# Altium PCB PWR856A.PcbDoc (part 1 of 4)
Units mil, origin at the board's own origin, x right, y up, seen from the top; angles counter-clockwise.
Board outline 4000 x 4000 mil, 8 copper layers (Top Layer, Signal Layer 1, Signal Layer 2, Signal Layer 3, Signal Layer 4, Signal Layer 5, Signal Layer 6, Bottom Layer), stack 60.4 mil thick; 246 components, 78 nets, 563 pads, 817 vias.
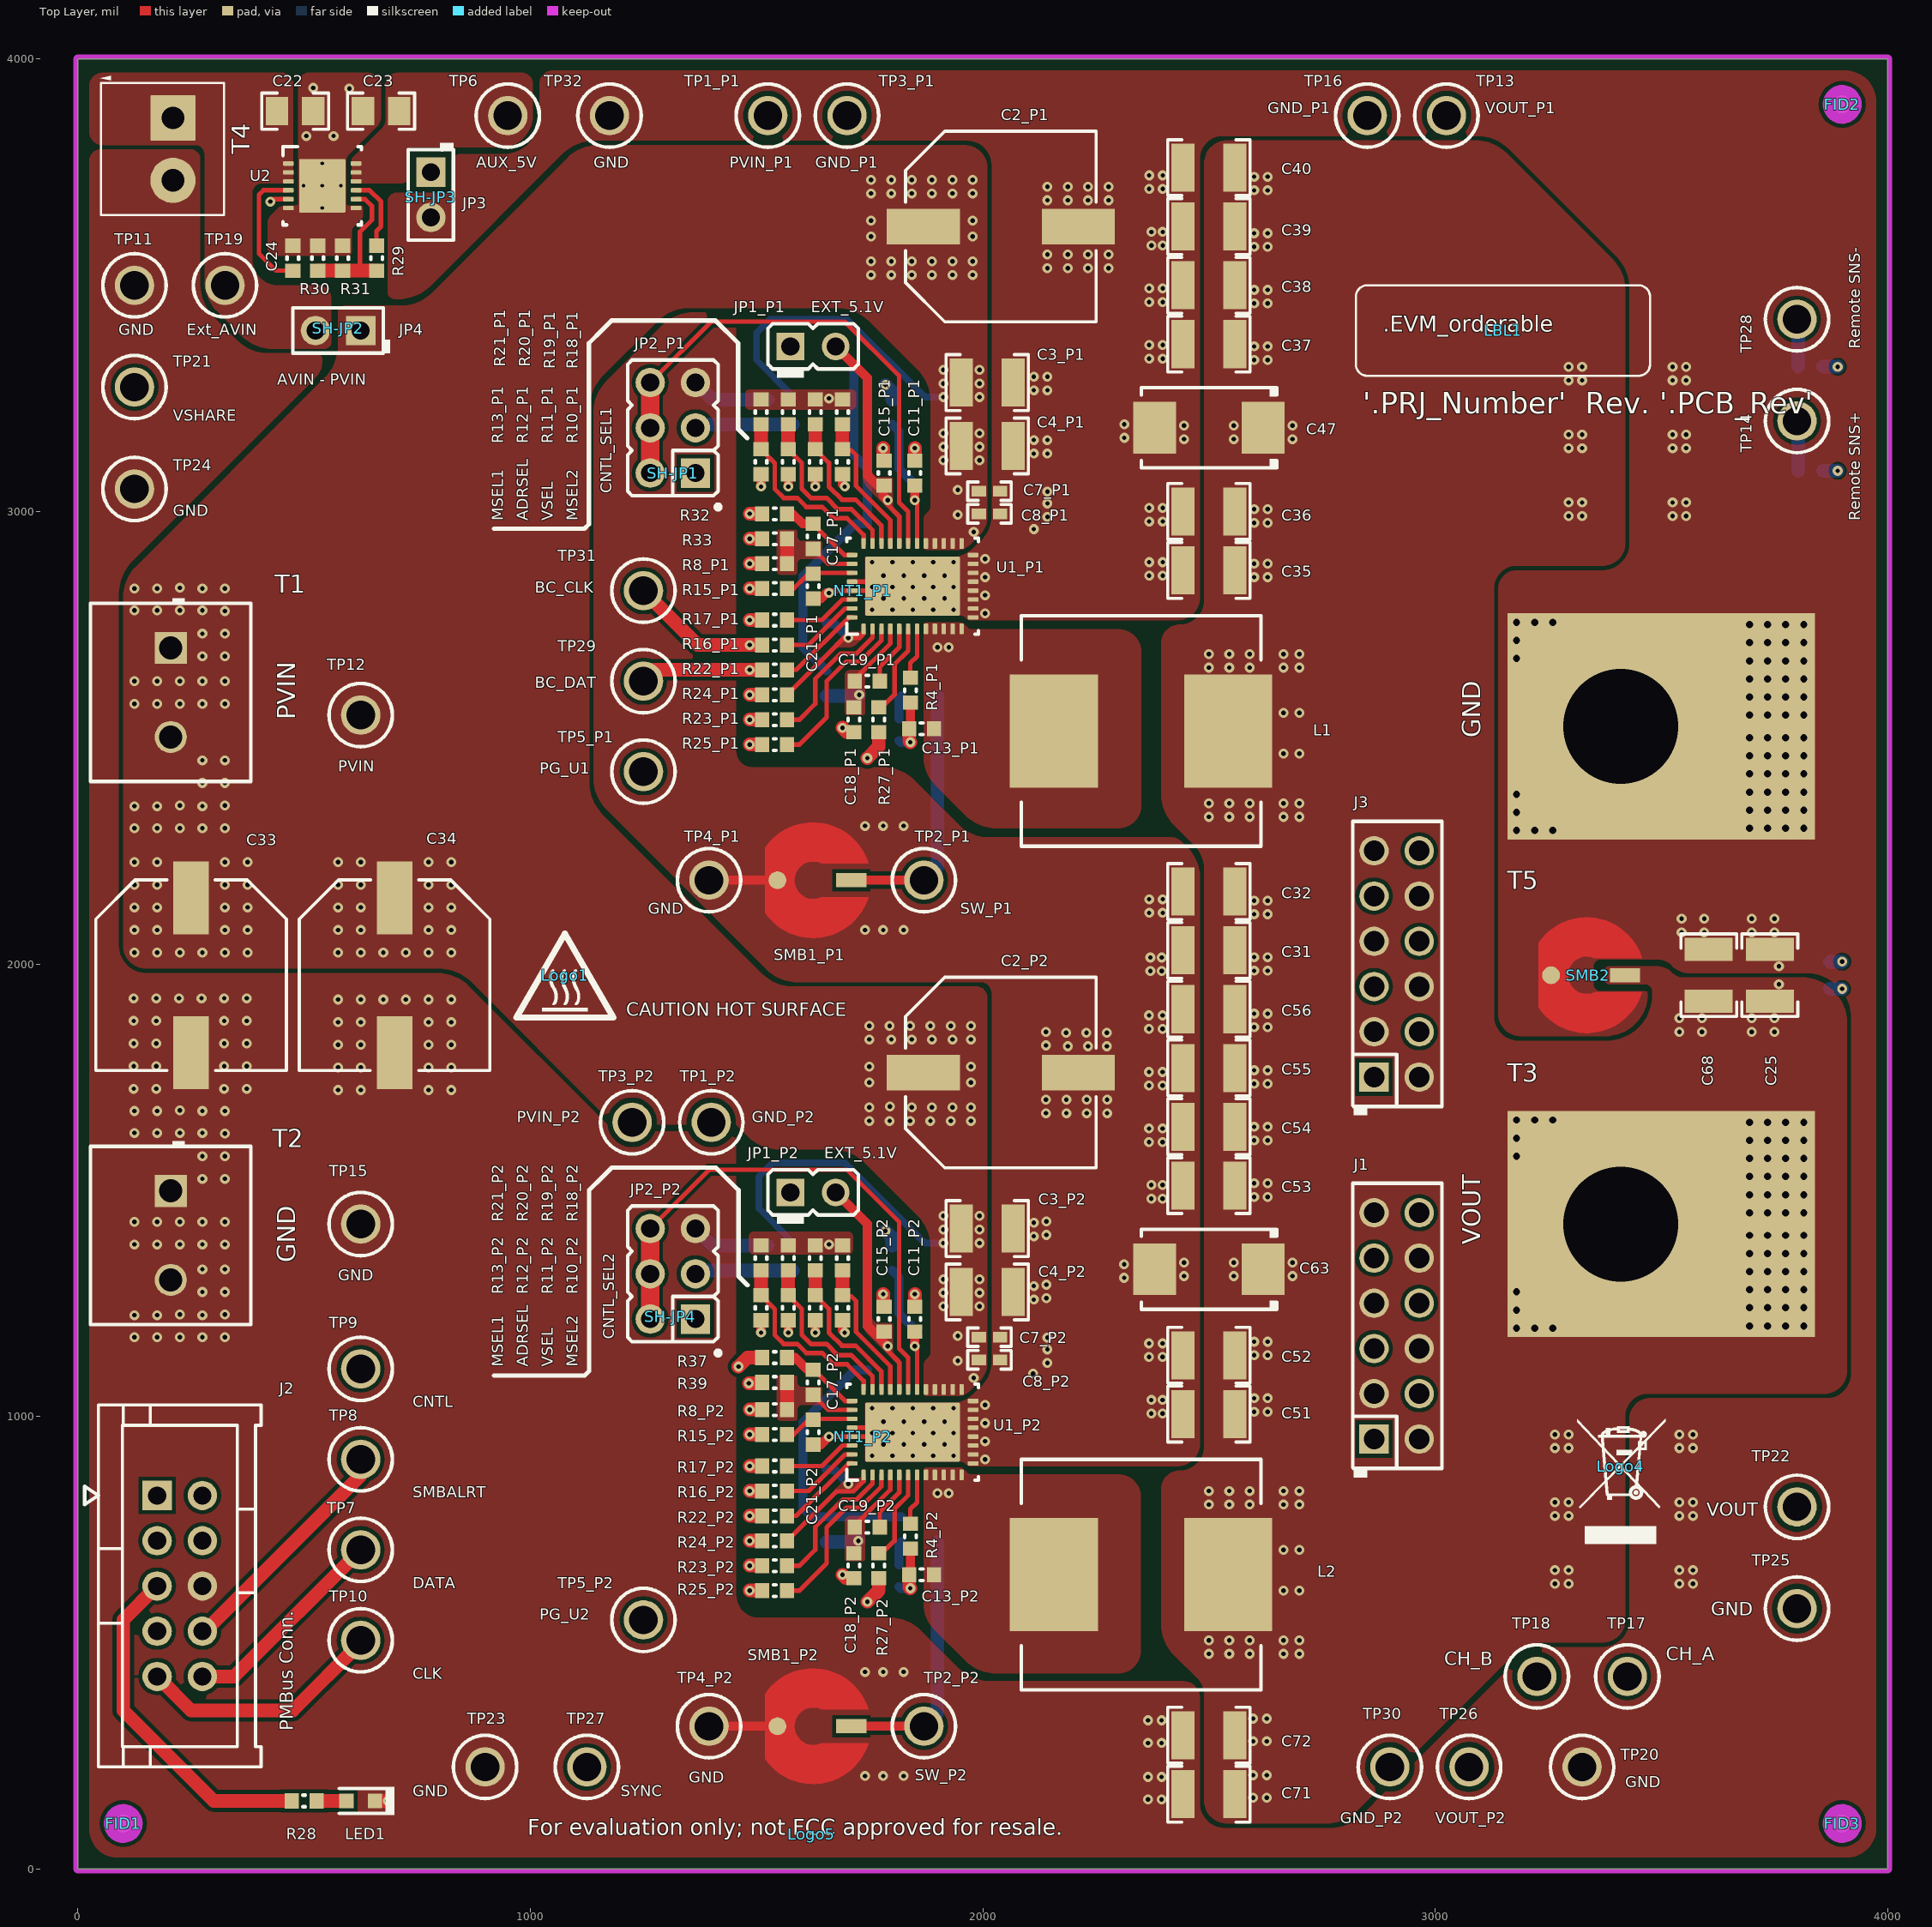
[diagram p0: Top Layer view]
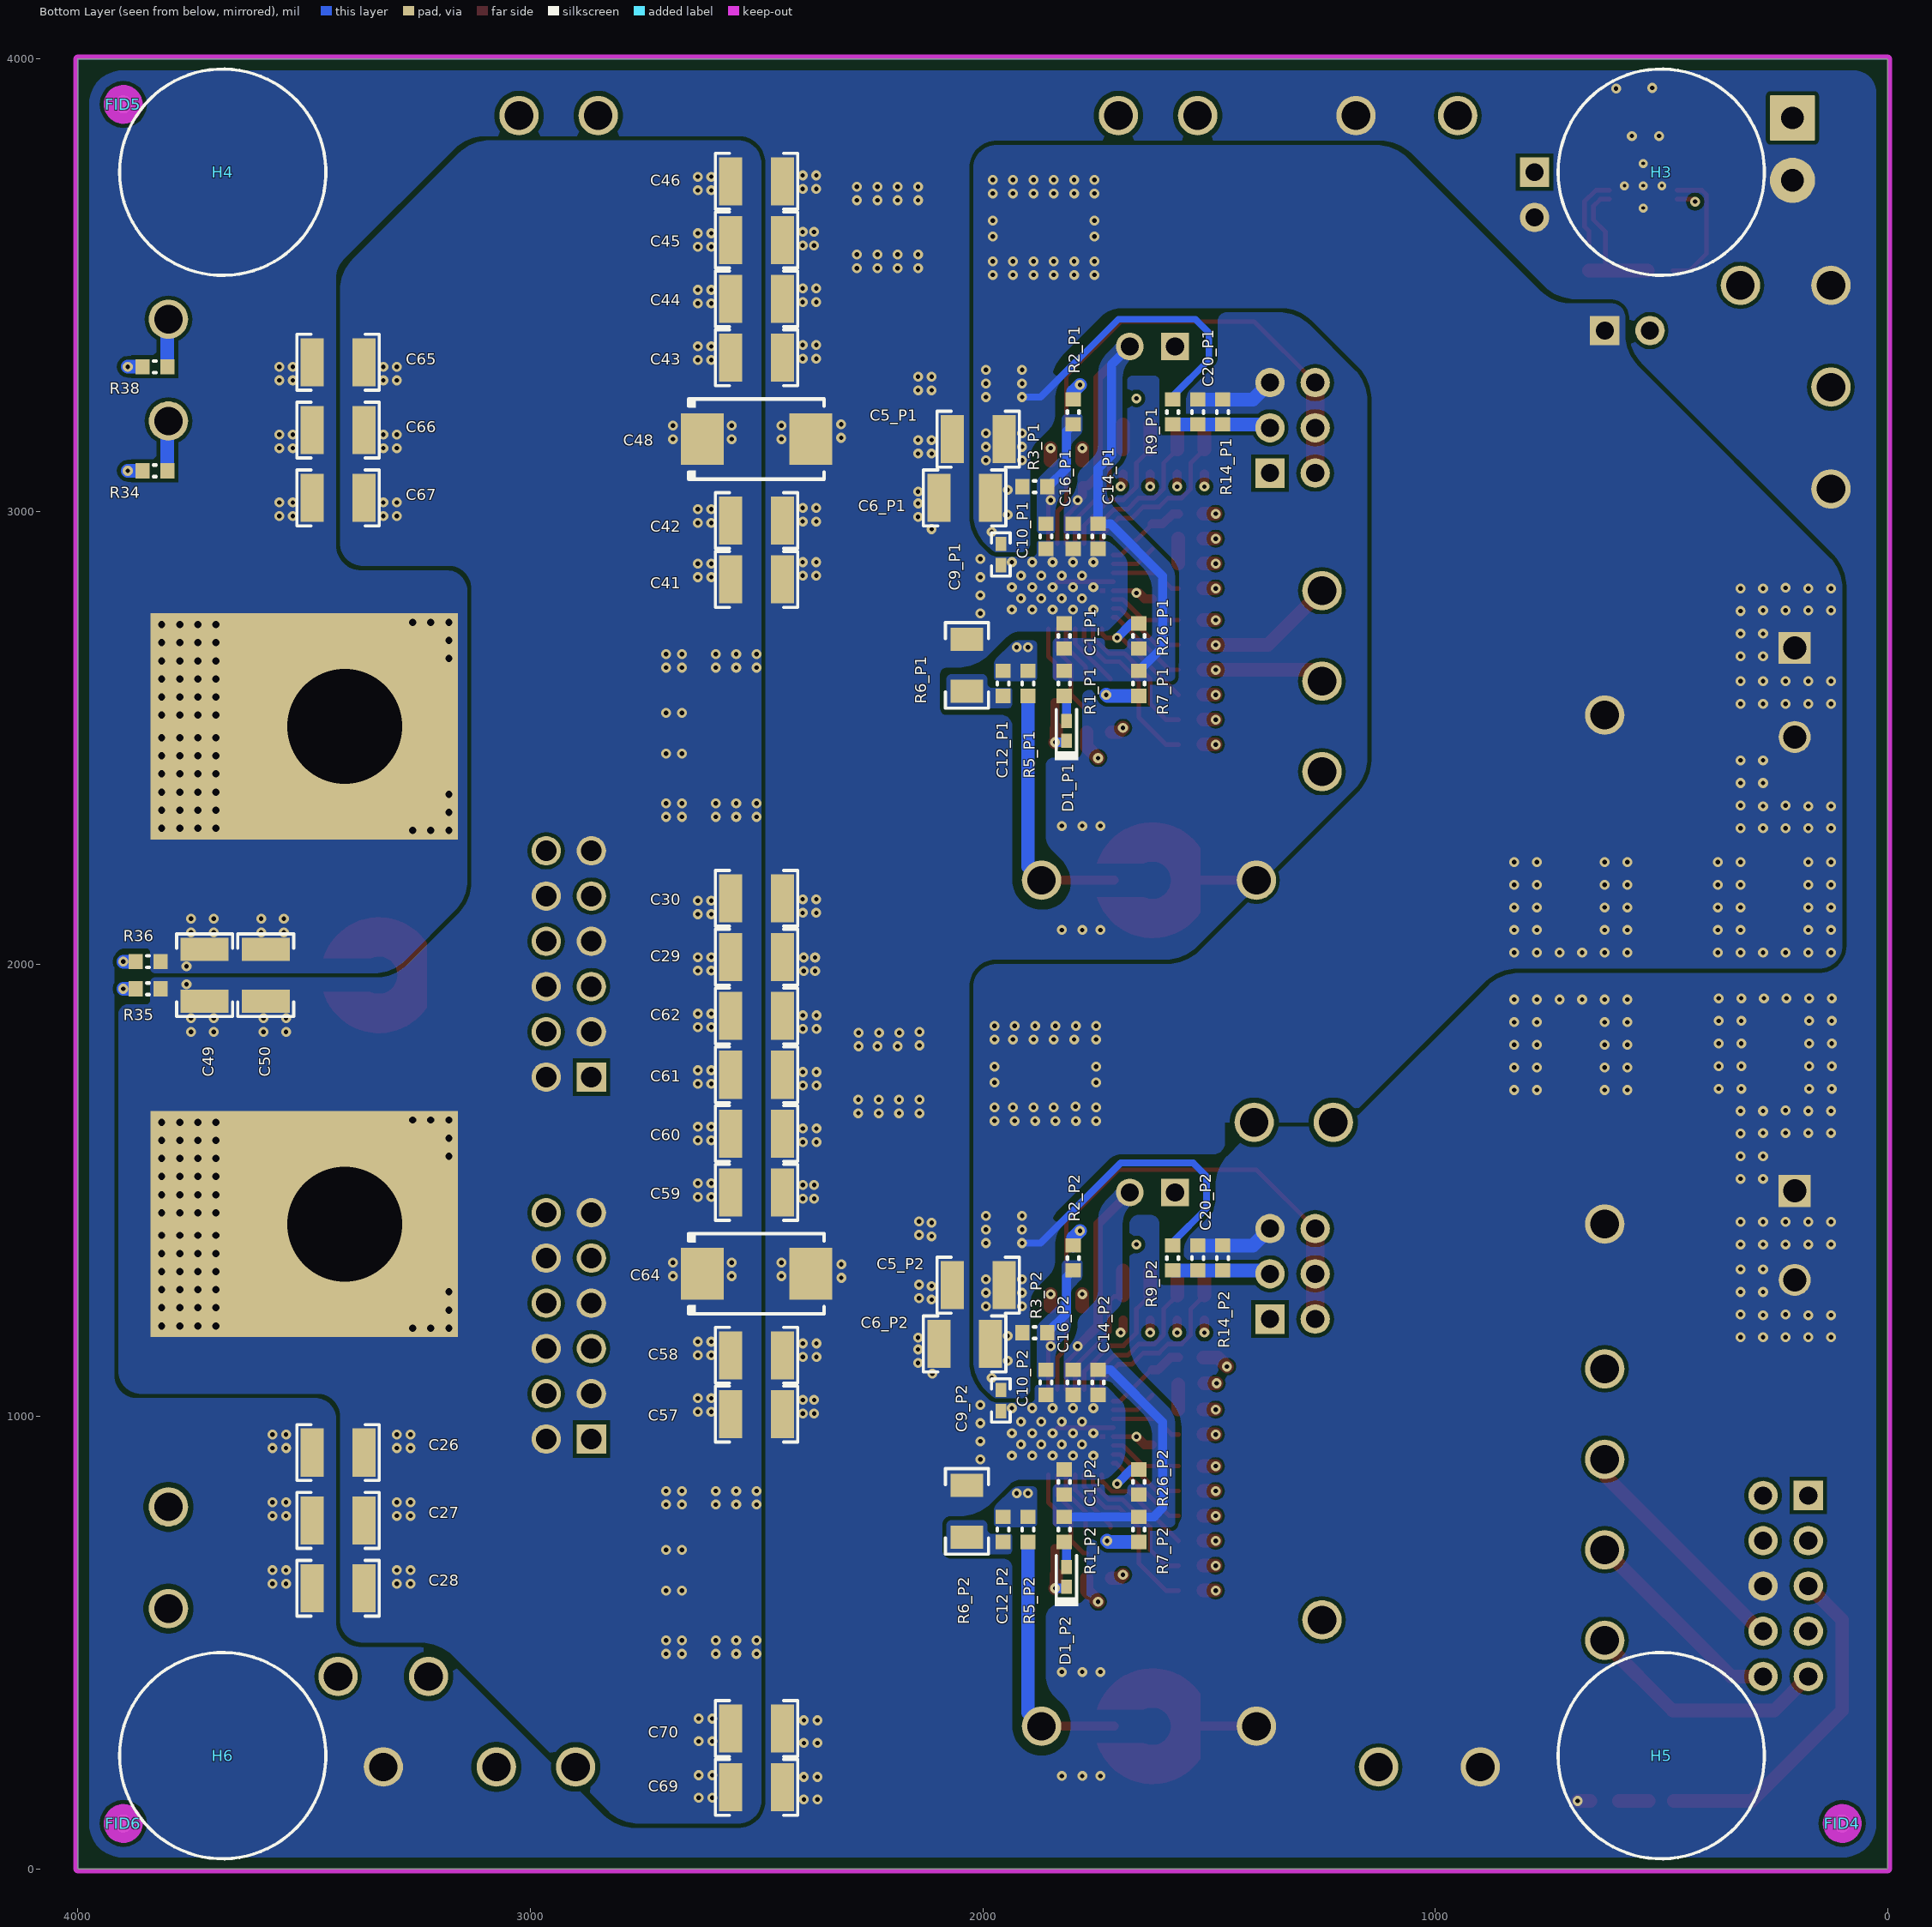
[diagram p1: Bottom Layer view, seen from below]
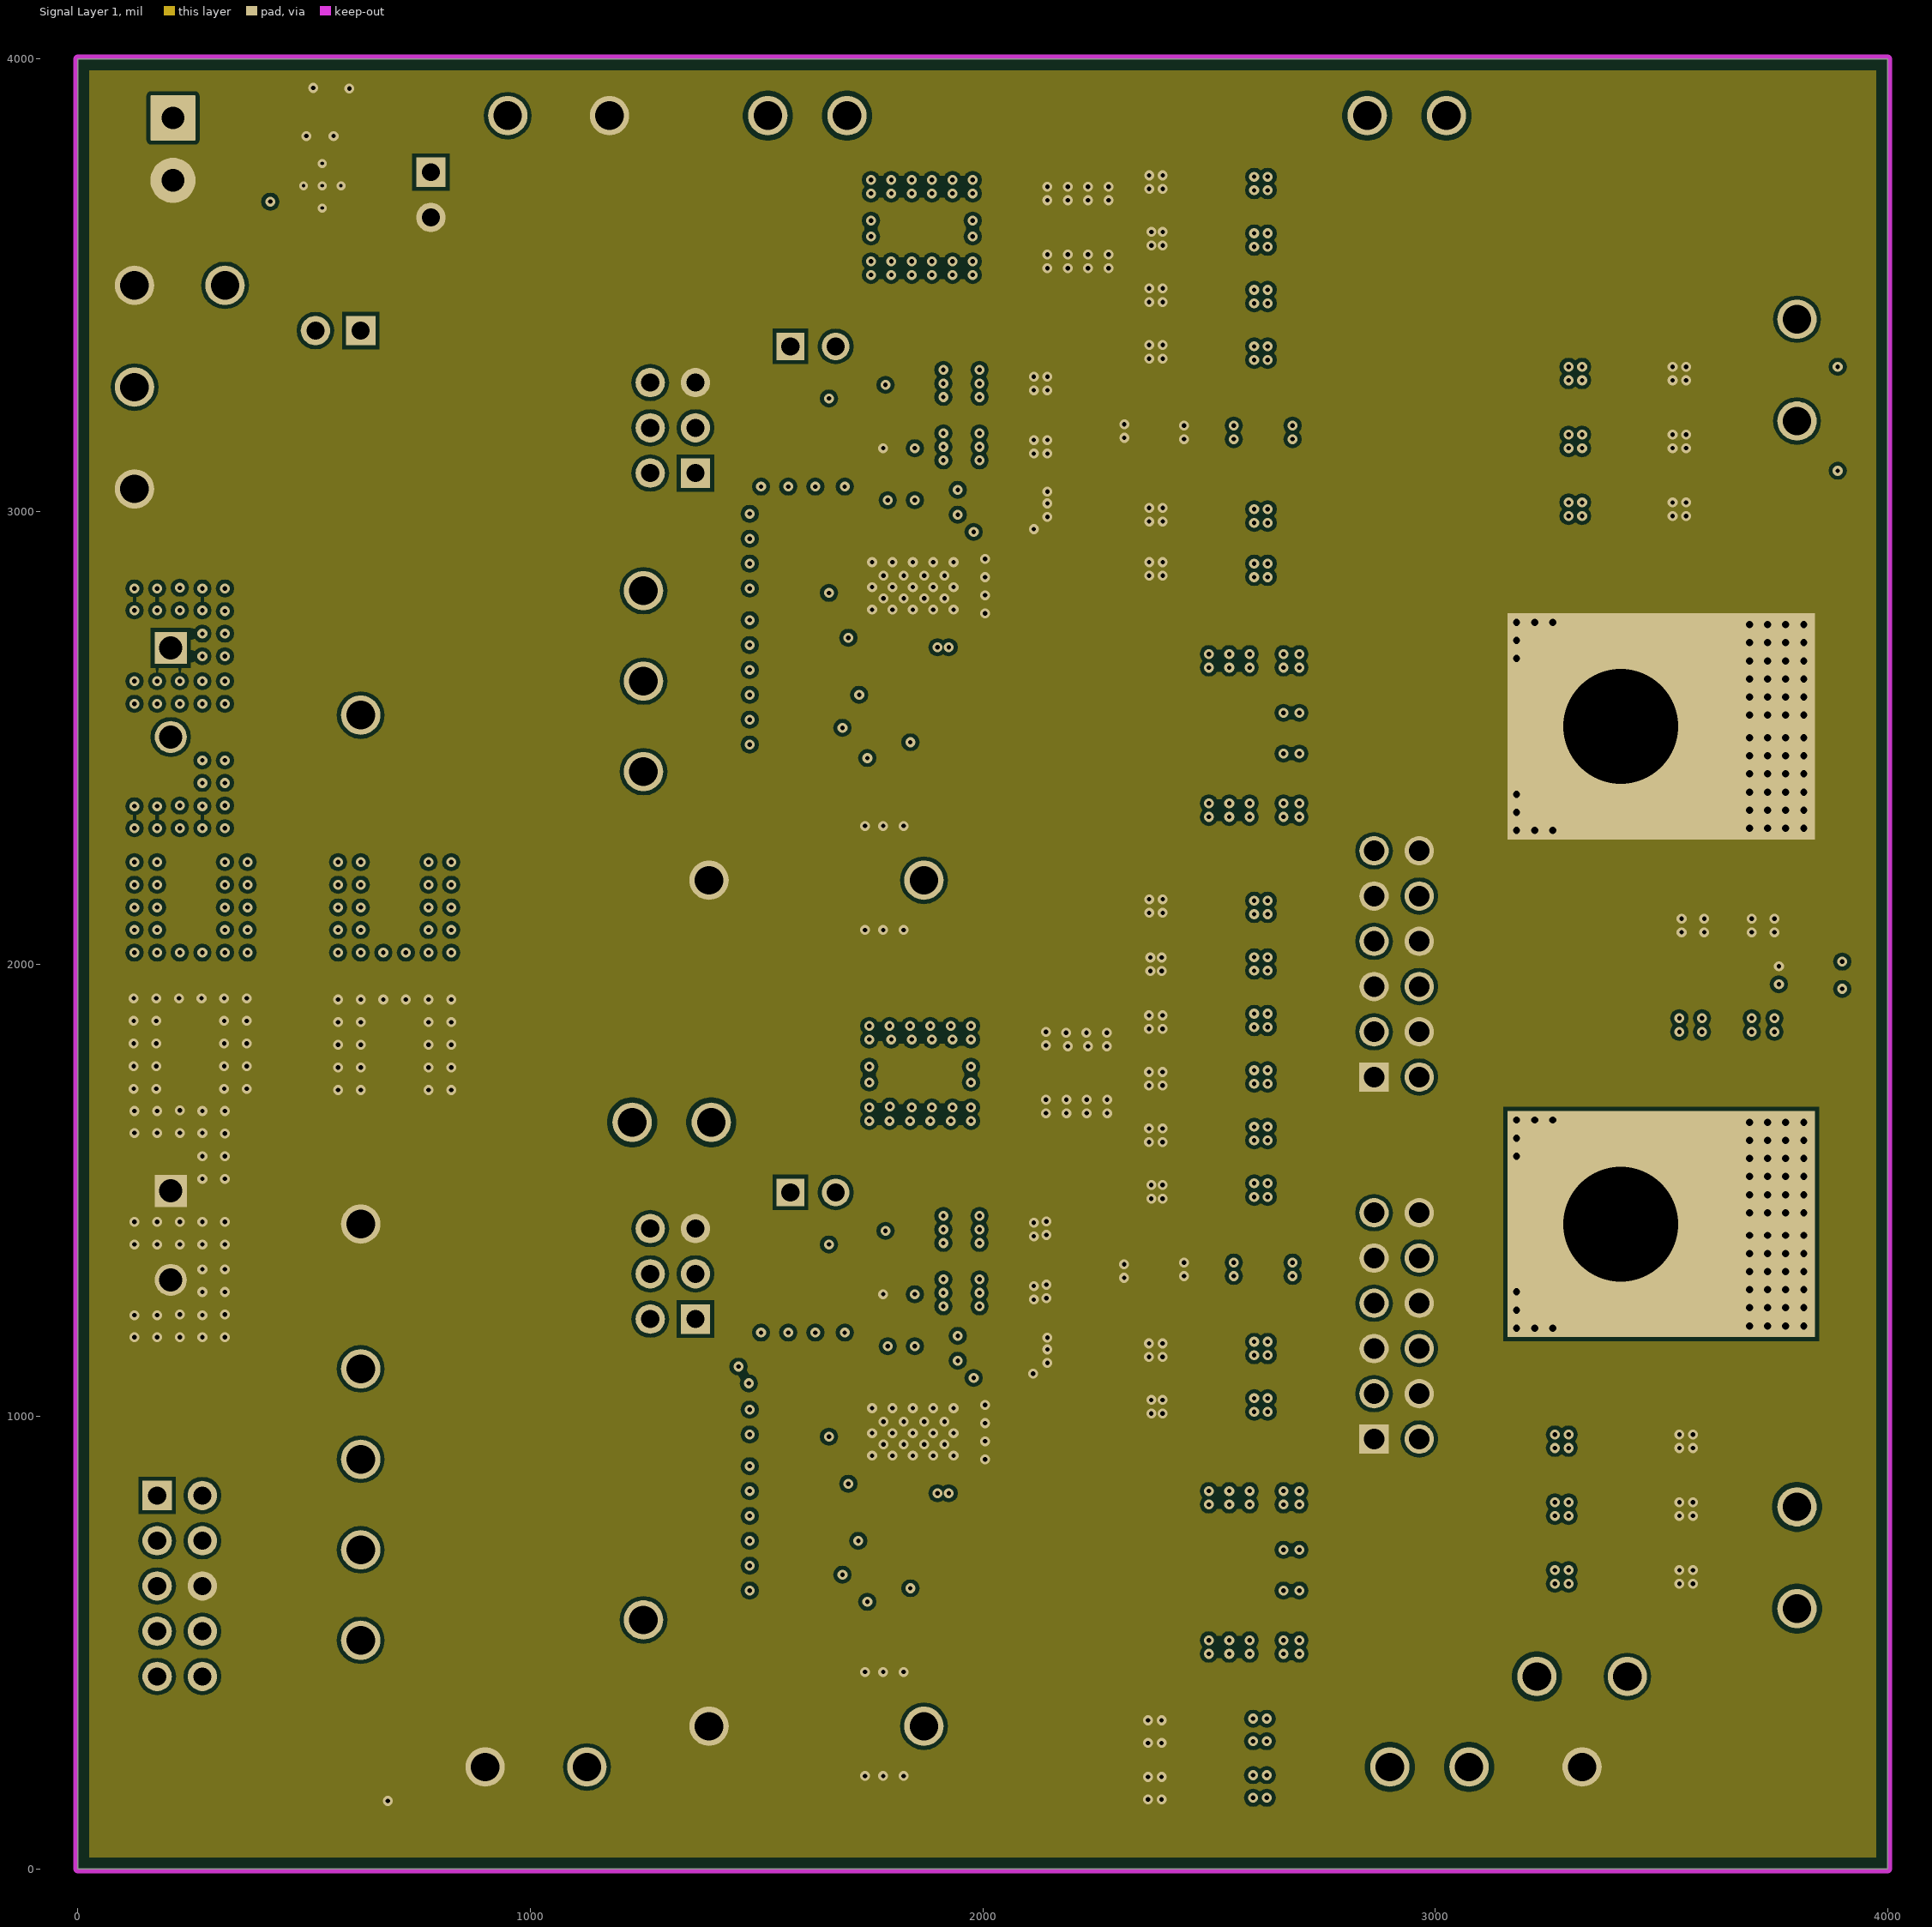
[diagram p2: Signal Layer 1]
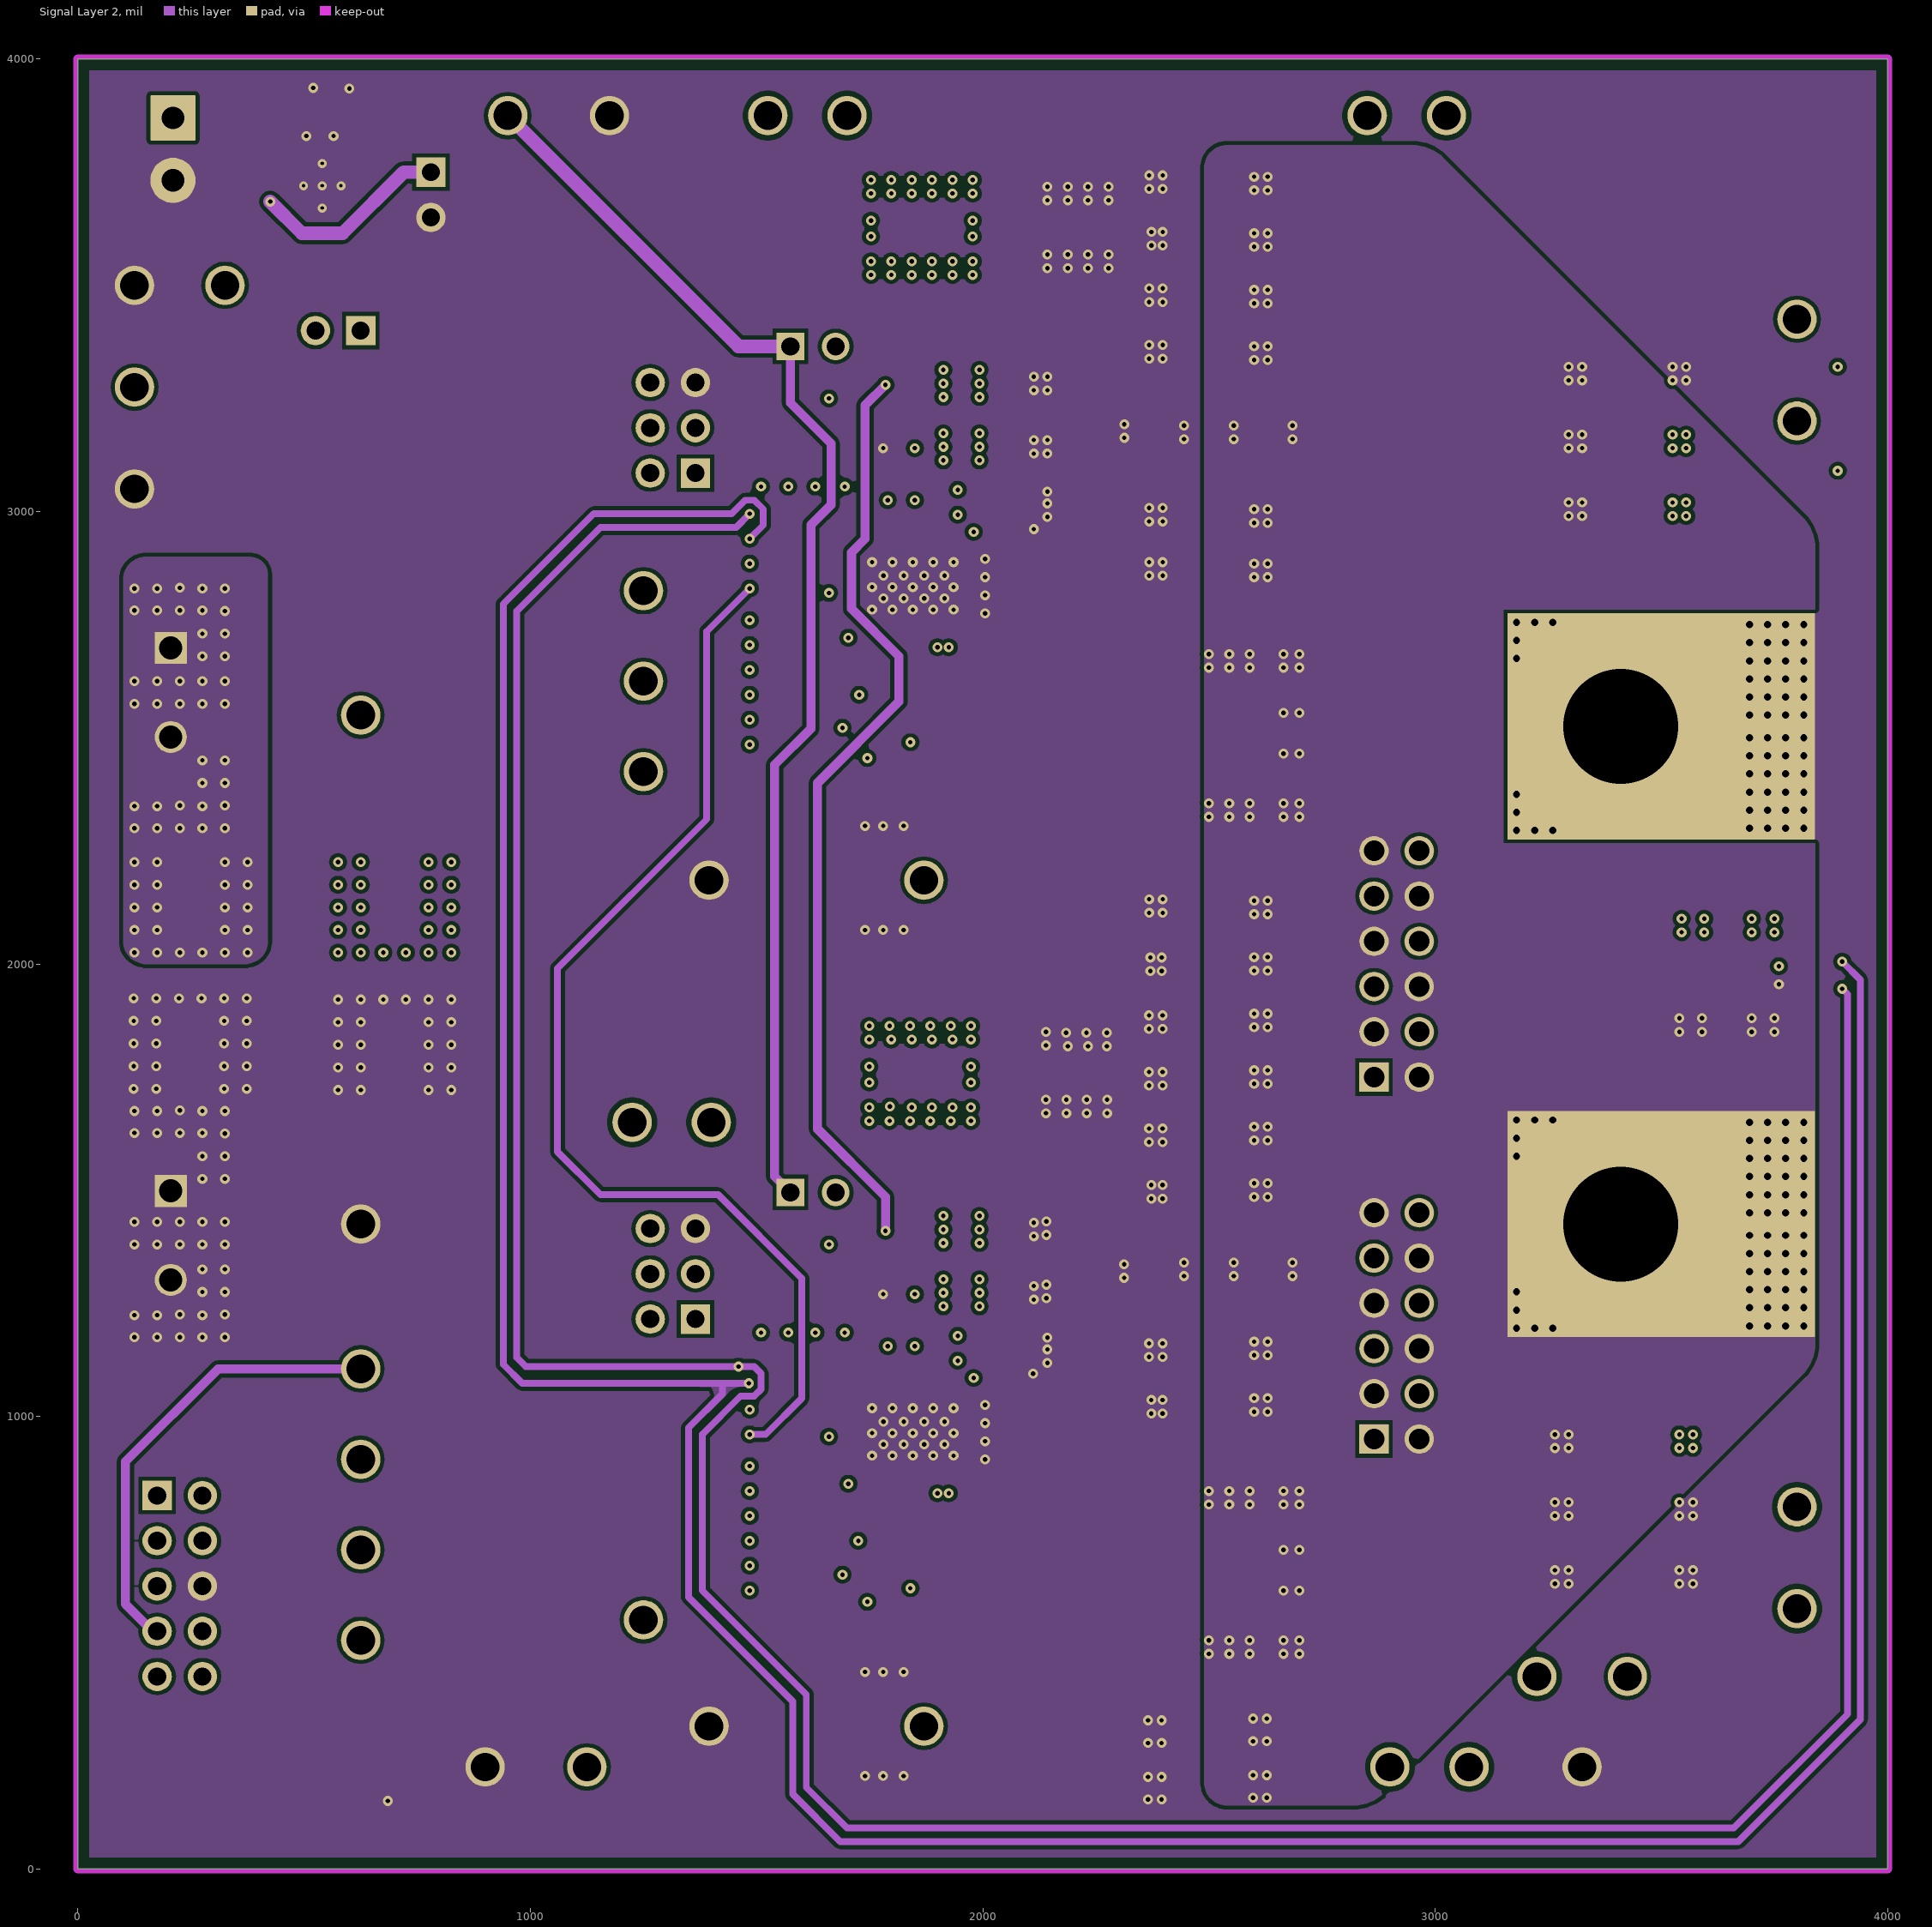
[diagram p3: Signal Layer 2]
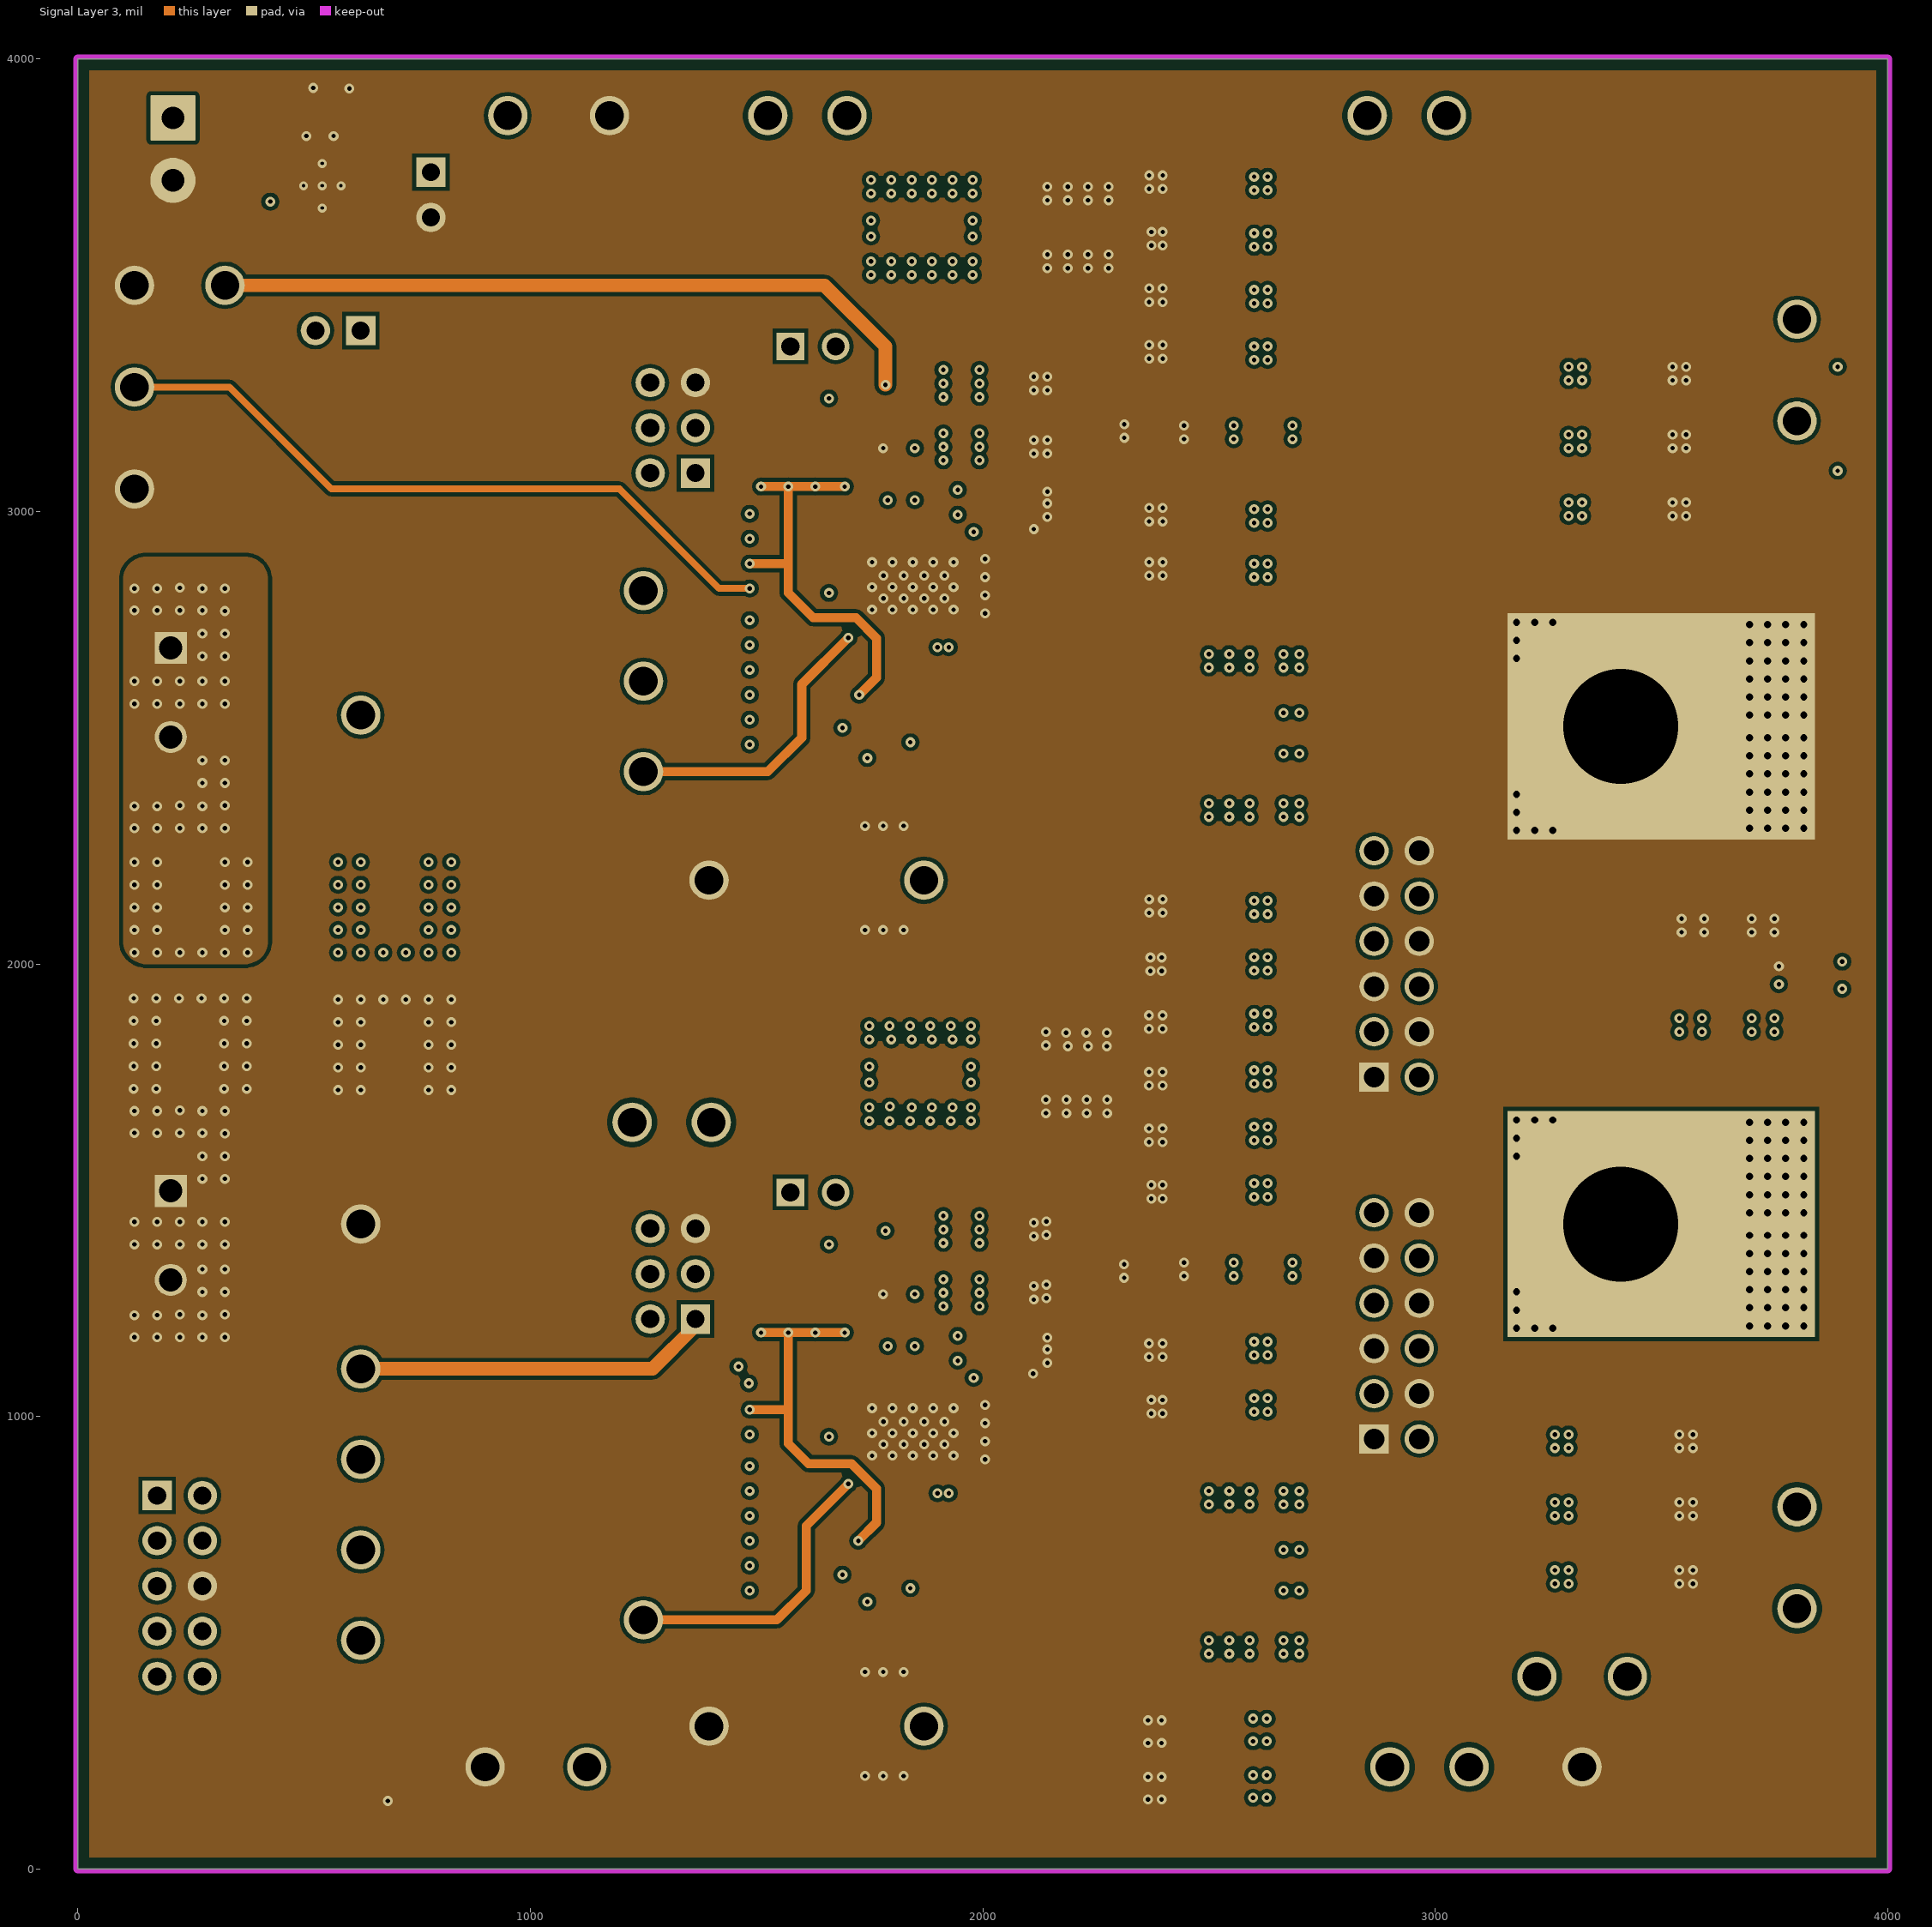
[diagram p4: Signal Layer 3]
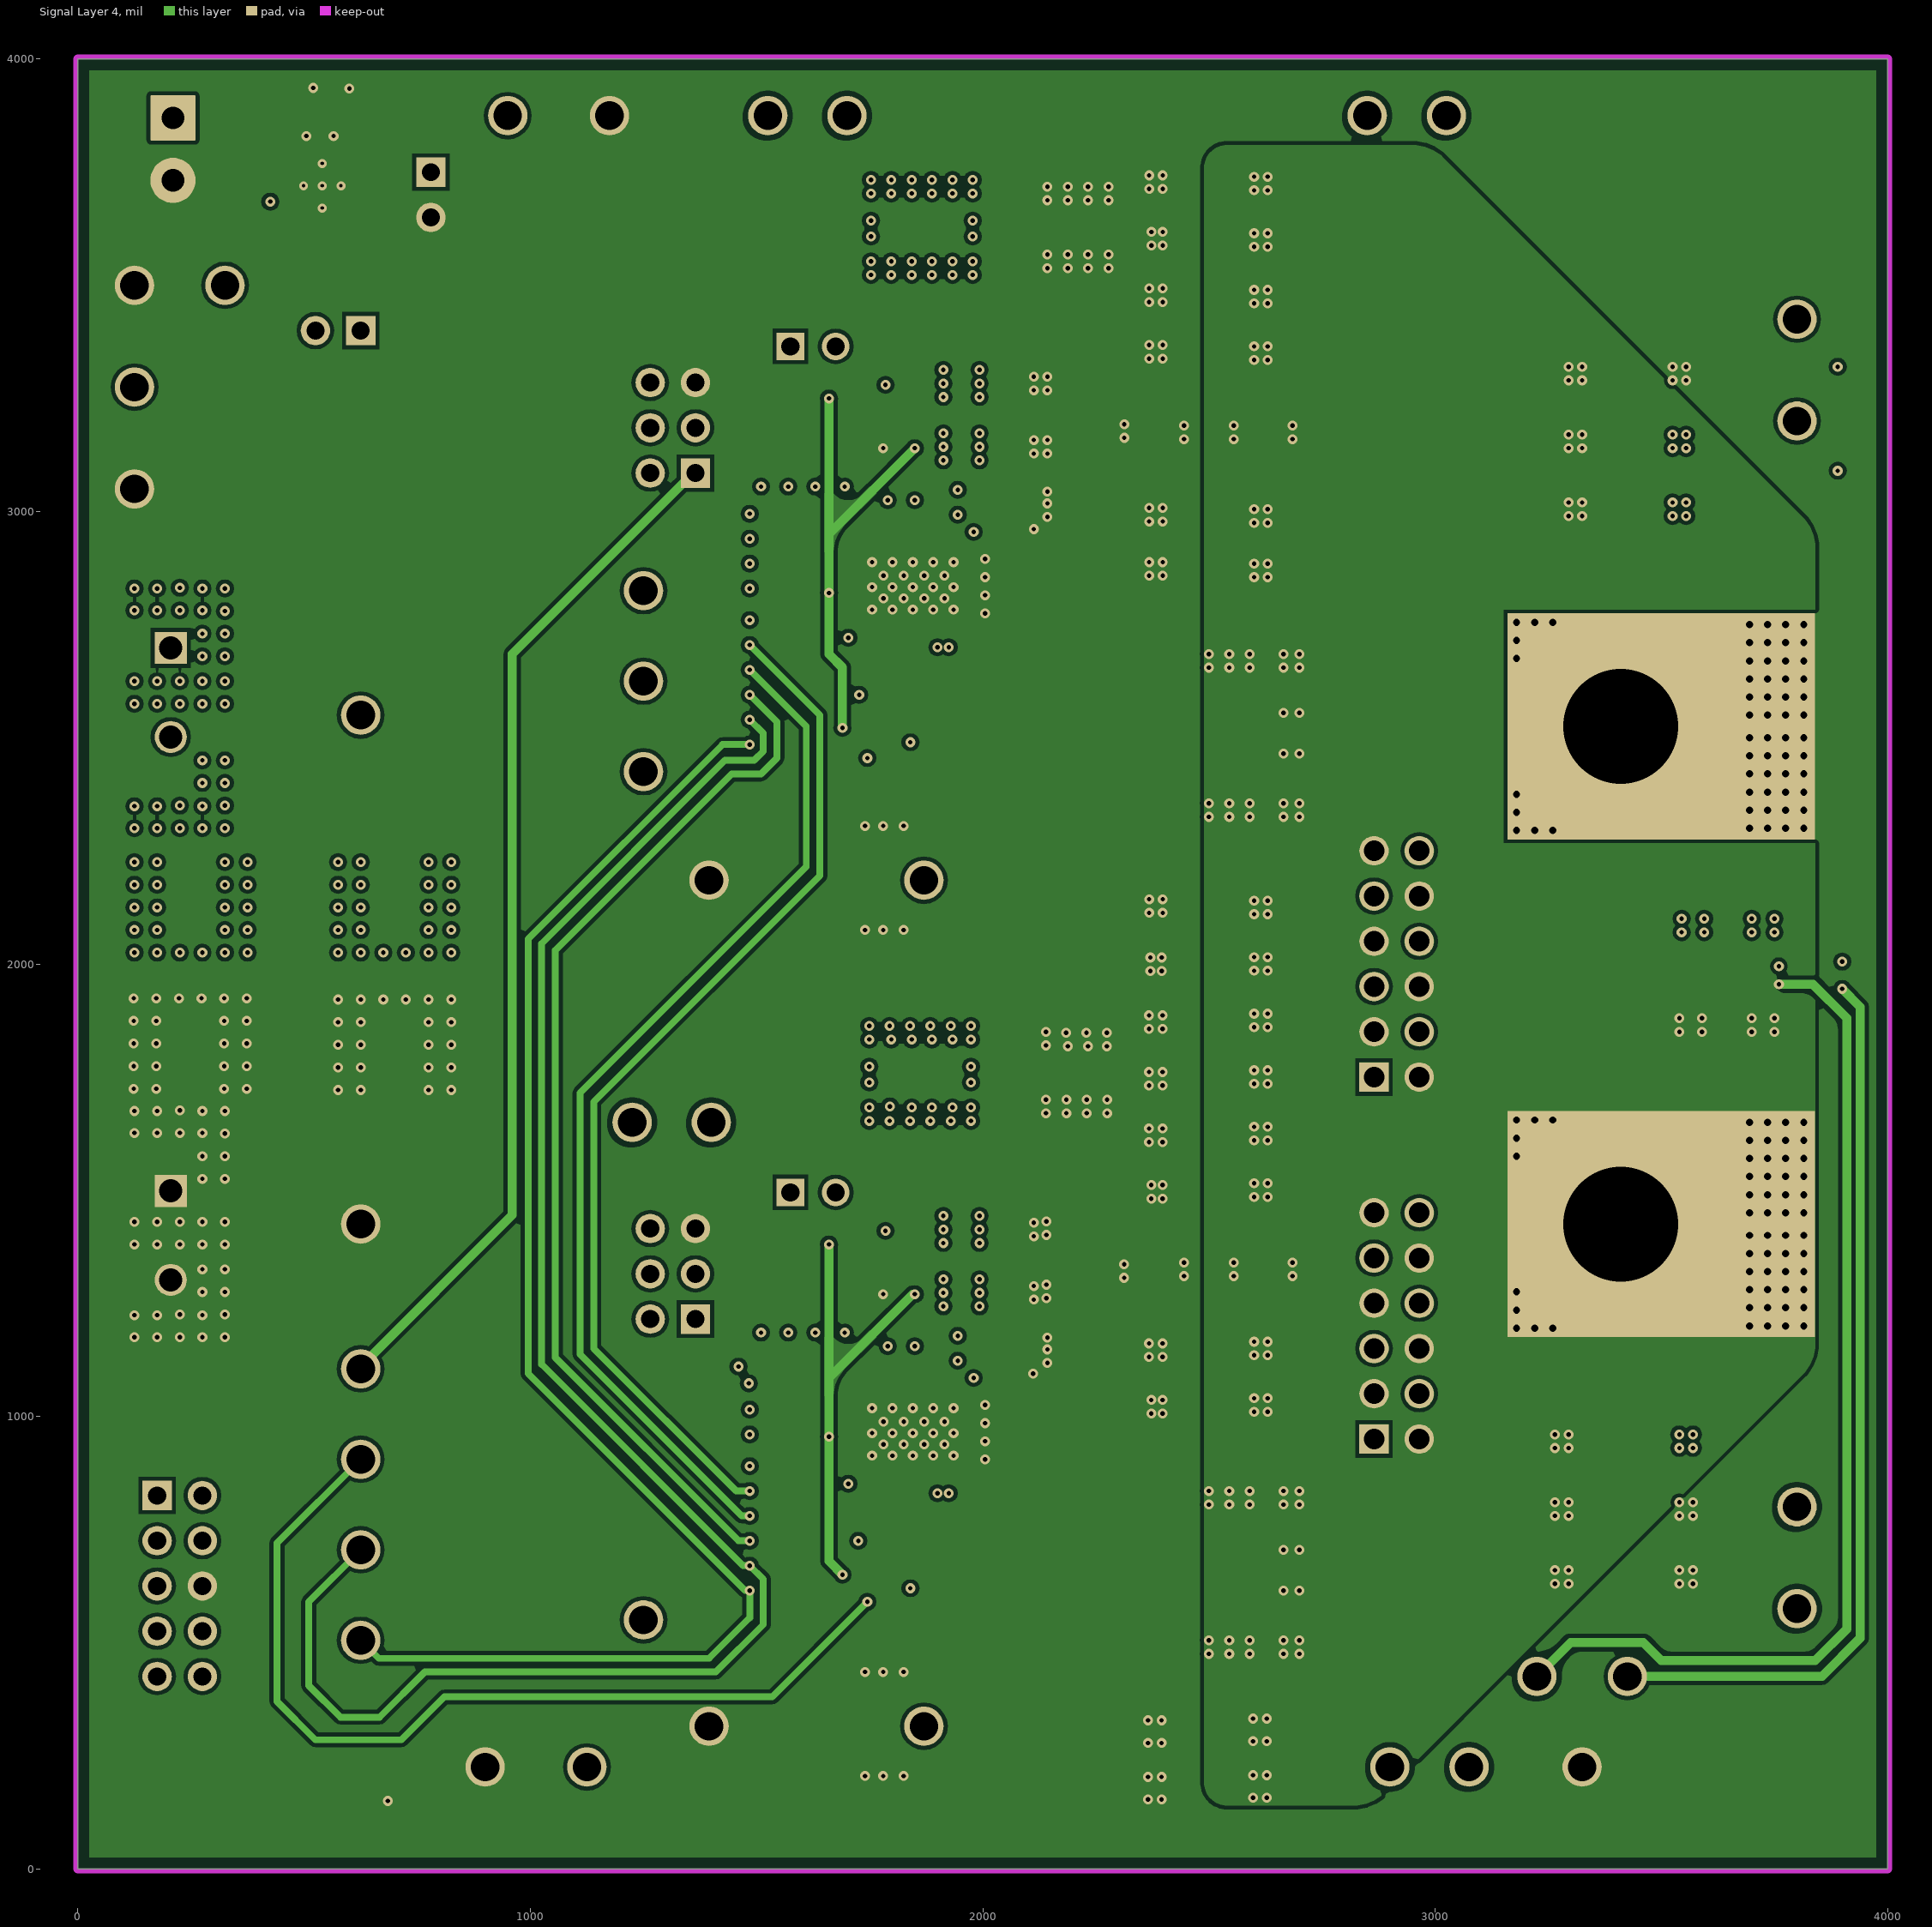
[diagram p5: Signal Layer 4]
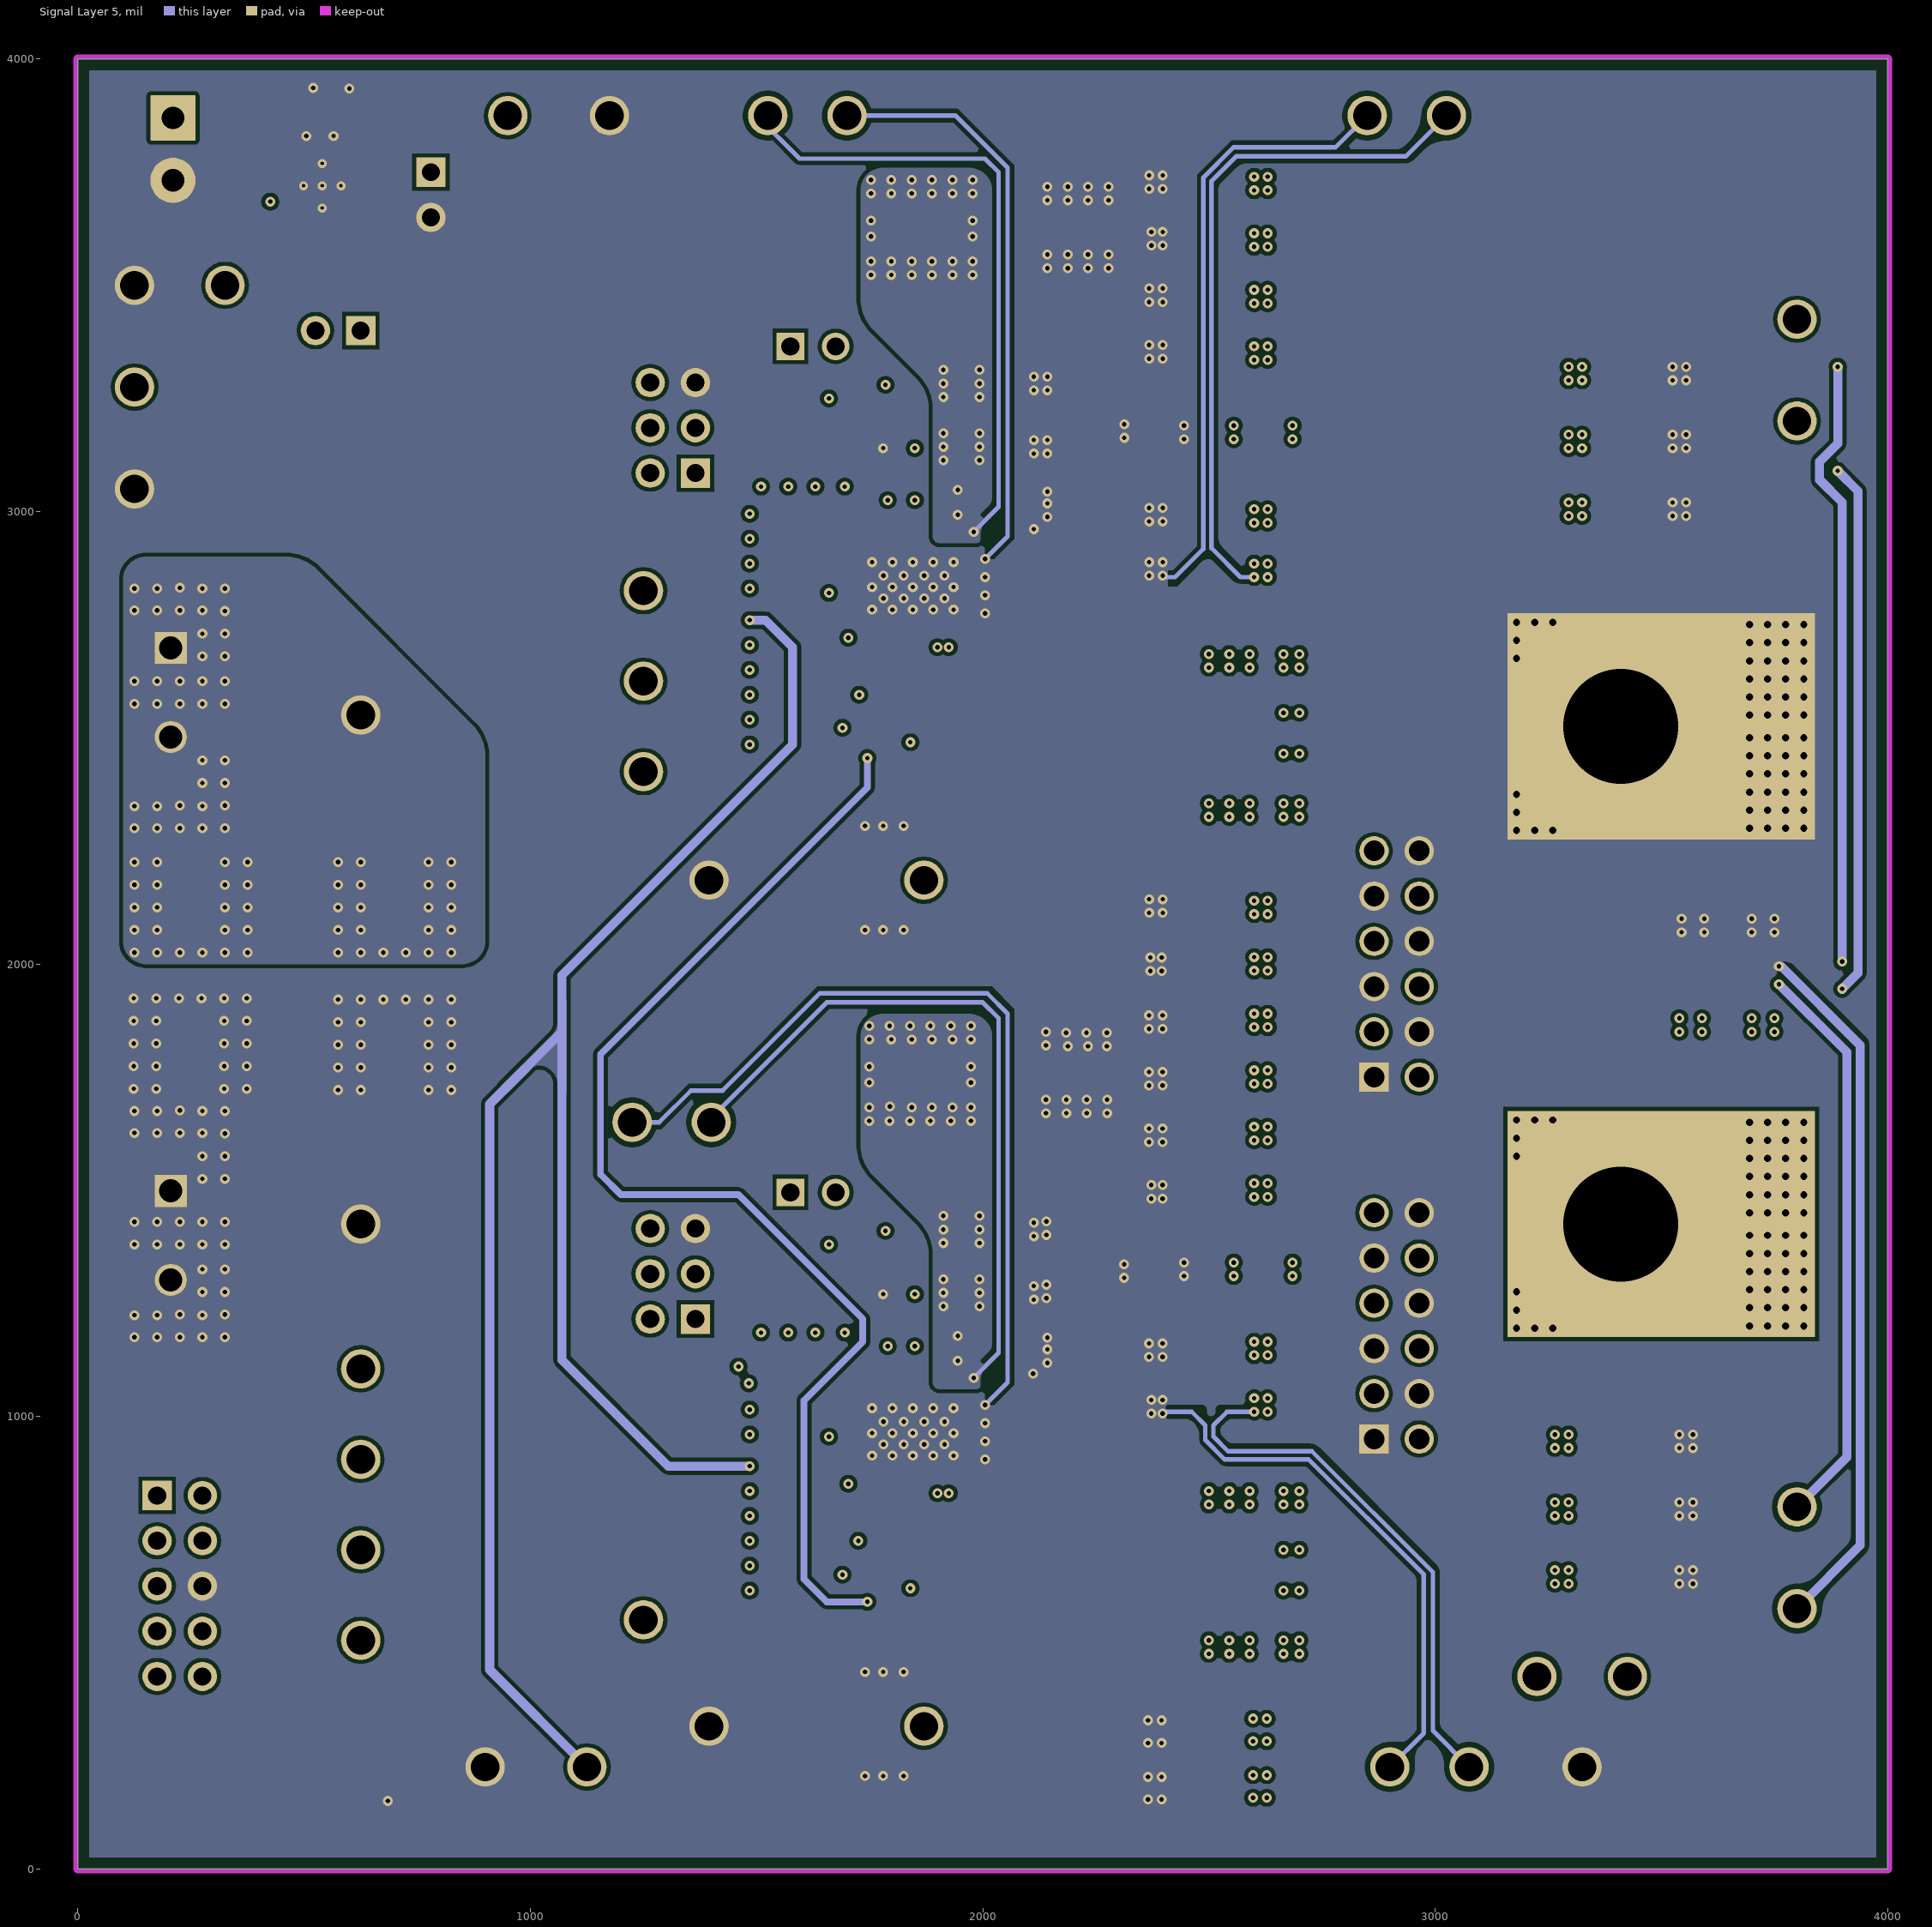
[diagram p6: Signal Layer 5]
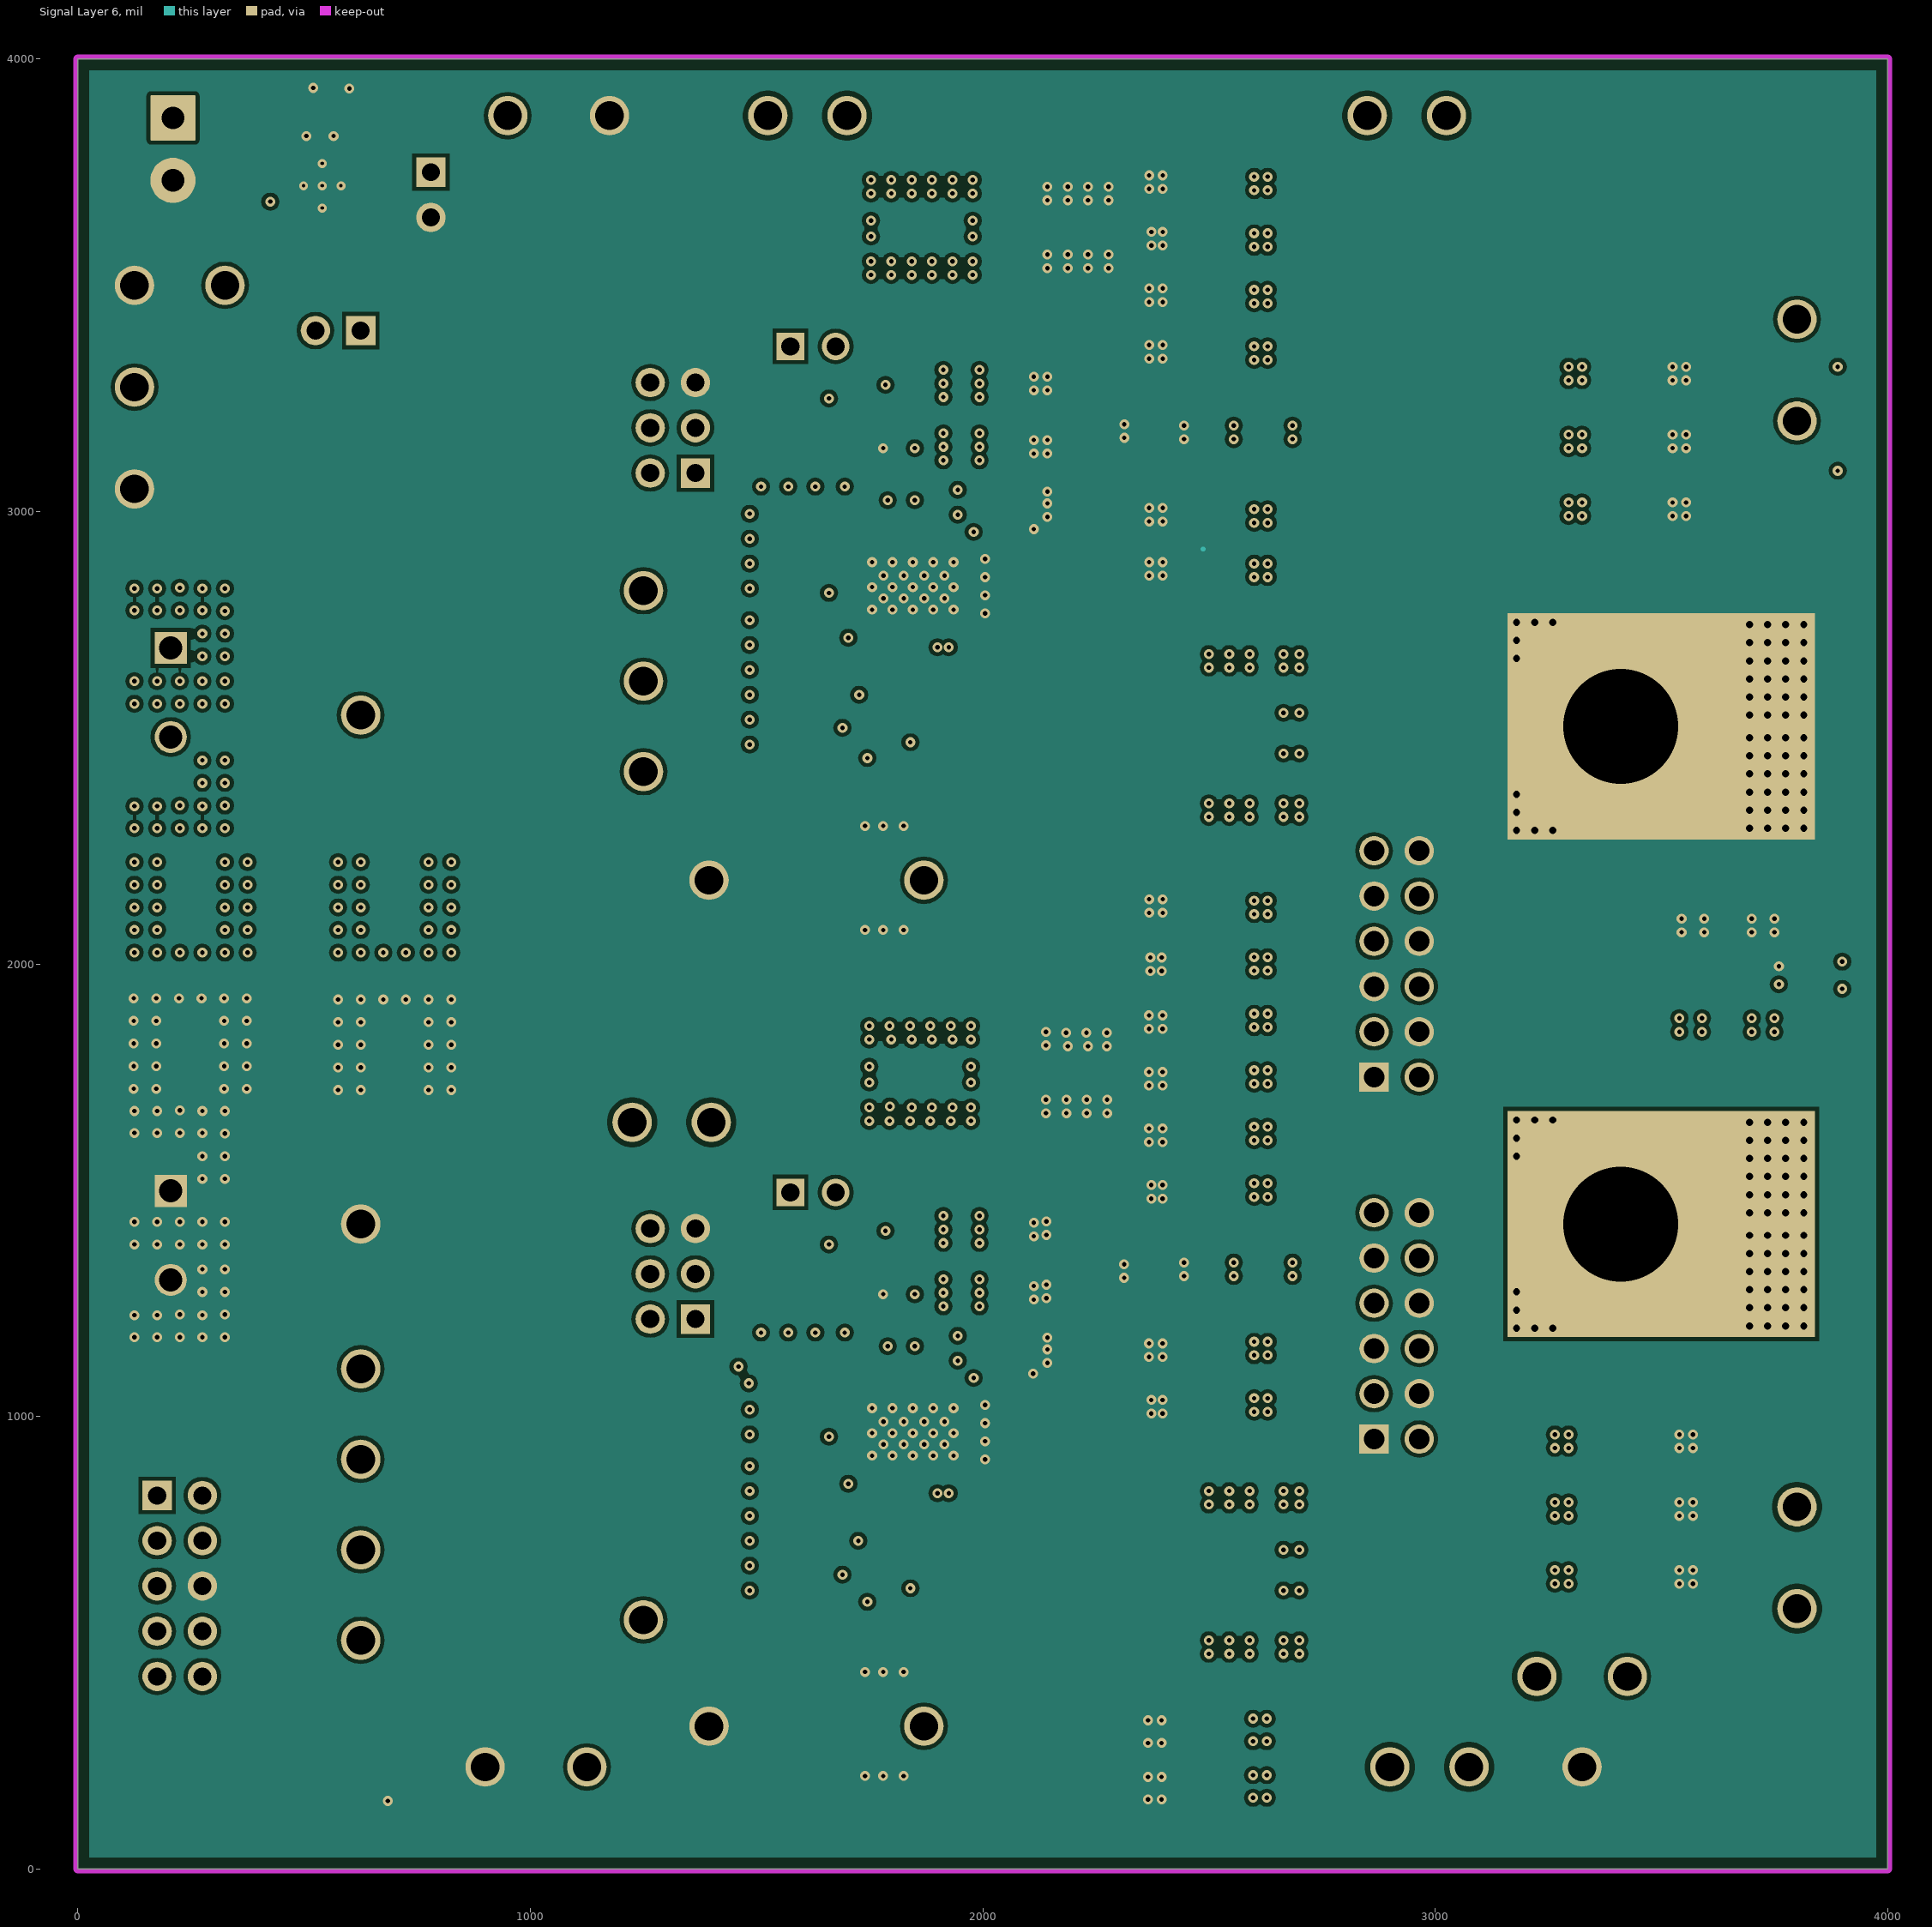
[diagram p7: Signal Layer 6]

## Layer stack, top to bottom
Top Solder: solder mask 0.5, Solder Resist, Dk 3.3
Top Layer: signal copper 2.8
Dielectric 1: prepreg 5, FR-4 High TG, Dk 4.2
Signal Layer 1: signal copper 2.8
Dielectric 2: core 6, FR-4 High TG, Dk 4.2
Signal Layer 2: signal copper 2.8
Dielectric 3: prepreg 5, FR-4 High TG, Dk 4.2
Signal Layer 3: signal copper 2.8
Dielectric 5: core 6, FR-4 High TG, Dk 4.2
Signal Layer 4: signal copper 2.8
Dielectric 4: prepreg 5, FR-4 High TG, Dk 4.2
Signal Layer 5: signal copper 2.8
Dielectric 6: core 6, FR-4 High TG, Dk 4.2
Signal Layer 6: signal copper 2.8
Dielectric 7: prepreg 5, FR-4 High TG, Dk 4.2
Bottom Layer: signal copper 2.8
Bottom Solder: solder mask 0.5, Solder Resist, Dk 3.3

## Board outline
0,0 4000,0 4000,4000 0,4000

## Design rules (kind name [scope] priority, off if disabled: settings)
AcuteAngle [All] p1: minimum=4.50000000000000E+0001 checktracksonly=TRUE
AssemblyTestPointUsage [All] p1: valid=2
BoardOutlineClearance BoardOutlineClearance_OutBoardText [IsText And IsFree And OnSignal And InRegionRelative(0,-1000,2000,0)] p1: gap=0 ignorepadtopadclearanceinfootprint=FALSE
BoardOutlineClearance BoardOutlineClearance_MountingHoles [OnCopper and InComponentClass('Mounting Holes')] p2: gap=40 ignorepadtopadclearanceinfootprint=FALSE
BoardOutlineClearance BoardOutlineClearance_Poly [OnCopper and IsPoly] p3: gap=25 ignorepadtopadclearanceinfootprint=FALSE
BoardOutlineClearance [OnCopper and Not InComponentClass('Logo') and not InComponentClass('FiducialMark') and not InRegion(1000,500,4000,800) and not InPoly] p4: gap=50 ignorepadtopadclearanceinfootprint=FALSE
Clearance Clearance_Fuducial [IsKeepOut and InComponentClass('FiducialMark') vs IsPad and InComponentClass('FiducialMark')] p1: gap=0 ignorepadtopadclearanceinfootprint=FALSE
Clearance Clearance_Keepouts [((IsTrack Or IsArc) And Not InPoly) And IsFree and IsKeepOut vs ((IsTrack Or IsArc) And Not InPoly) And IsFree and IsKeepOut] p2: gap=0 ignorepadtopadclearanceinfootprint=FALSE
Clearance Clearance_Poly [InPolygon] p3: gap=8.5 ignorepadtopadclearanceinfootprint=FALSE except(0: Arc-Hole Track-Hole SMDPad-Hole THPad-Hole Via-Hole Fill-Hole Poly-Hole Region-Hole Text-Hole)
Clearance [All] p4: gap=8 ignorepadtopadclearanceinfootprint=FALSE except(0: Arc-Hole Track-Hole SMDPad-Hole THPad-Hole Via-Hole Fill-Hole Poly-Hole Region-Hole Text-Hole)
ComponentClearance ComponentClearance_Bumpon [HasFootprint('Bumpon_SJ5003Transparent') vs HasFootprint('Fiducial10-20')] p1: gap=0 collisioncheckmode=3 verticalgap=0 showdistances=FALSE
ComponentClearance ComponentClearance_NetTie [Incomponent ('U1_P1') or Incomponent ('U1_P2') vs Incomponent ('NT1_P1') or Incomponent ('NT1_P2')] p2: gap=0 collisioncheckmode=3 verticalgap=0 showdistances=FALSE
ComponentClearance ComponentClearance_MountingHoles_FiducialMarks [InComponentClass('Mounting Holes') vs InComponentClass('FiducialMark')] p3: gap=50 collisioncheckmode=3 verticalgap=10 showdistances=FALSE
ComponentClearance ComponentClearance_Shunt [InComponentClass('Header') vs InComponentClass('Shunt')] p4: gap=0 collisioncheckmode=3 verticalgap=0 showdistances=FALSE
ComponentClearance ComponentClearance_Logo [InComponentClass('Logo')] p5: gap=50 collisioncheckmode=3 verticalgap=10 showdistances=FALSE
ComponentClearance ComponentClearance_ScrewToNut [(HasFootprint('NY PMS 440 0025 PH')) vs (HasFootprint('Keystone_1902C'))] p6: gap=5 collisioncheckmode=3 verticalgap=10 showdistances=FALSE
ComponentClearance ComponentClearance_MountingHoles [InComponentClass('Mounting Holes')] p7: gap=250 collisioncheckmode=3 verticalgap=100000 showdistances=FALSE
ComponentClearance ComponentClearance_SmallPassives [HasFootprint('0201*') or HasFootprint('0402*') or HasFootprint('0508') or HasFootprint('0603*') or HasFootprint('0612') or HasFootprint('0805*') or HasFootprint('0815*') or HasFootprint('0830*') or HasFootprint('1206*') or HasFootprint('1210*') or HasFootprint('1808*') or HasFootprint('1812*') or HasFootprint('1825*') or HasFootprint('2010*') or HasFootprint('2220*') or HasFootprint('2225*') or HasFootprint('2512*') or HasFootprint('2728*') or HasFootprint('3518*') vs HasFootprint('0201*') or HasFootprint('0402*') or HasFootprint('0508') or HasFootprint('0603*') or HasFootprint('0612') or HasFootprint('0805*') or HasFootprint('0815*') or HasFootprint('0830*') or HasFootprint('1206*') or HasFootprint('1210*') or HasFootprint('1808*') or HasFootprint('1812*') or HasFootprint('1825*') or HasFootprint('2010*') or HasFootprint('2220*') or HasFootprint('2225*') or HasFootprint('2512*') or HasFootprint('2728*') or HasFootprint('3518*')] p8: gap=15 collisioncheckmode=3 verticalgap=10 showdistances=FALSE
ComponentClearance ComponentClearance_THtoSMT [IsThruComponent vs IsSMTComponent] p9: gap=30 collisioncheckmode=3 verticalgap=30 showdistances=FALSE
ComponentClearance ComponentClearance_THtoTH [IsThruComponent vs IsThruComponent] p10: gap=30 collisioncheckmode=3 verticalgap=30 showdistances=FALSE
ComponentClearance [All] p11: gap=30 collisioncheckmode=3 verticalgap=10 showdistances=FALSE
DiffPairsRouting [All] p1: maxlimit=100 minlimit=10 mostfreqgap=10 toplayer_minwidth=15 toplayer_maxwidth=15 toplayer_prefwidth=15 midlayer1_minwidth=15 midlayer1_maxwidth=15 midlayer1_prefwidth=15 midlayer2_minwidth=15 midlayer2_maxwidth=15 midlayer2_prefwidth=15 midlayer3_minwidth=15 midlayer3_maxwidth=15 midlayer3_prefwidth=15 midlayer4_minwidth=15 midlayer4_maxwidth=15 midlayer4_prefwidth=15 midlayer5_minwidth=15 midlayer5_maxwidth=15 midlayer5_prefwidth=15 midlayer6_minwidth=15 midlayer6_maxwidth=15 midlayer6_prefwidth=15 bottomlayer_minwidth=15 bottomlayer_maxwidth=15 bottomlayer_prefwidth=15 maxuncoupledlength=1000
FabricationTestPointUsage TestPointUsage [All] p1: valid=2 allowmultiple=FALSE
FabricationTestpoint Testpoint [All] p1: side=3 testpointundercomponent=TRUE minsize=40 maxsize=100 preferedsize=60 minholesize=0 maxholesize=40 preferedholesize=32 testpointgrid=1 allowsidetop=TRUE allowsidebottom=TRUE usegrid=TRUE gridtolerance=0.01
FanoutControl Fanout_LCC [IsLCC] p1: bgadir=Out bgaviamode=Centered fanoutstyle=Auto fanoutdirection=Alternating viagrid=1 // Fanout_LCC (Default Rule)
FanoutControl Fanout_BGA [IsBGA] p2: bgadir=Out bgaviamode=Centered fanoutstyle=Auto fanoutdirection=Alternating viagrid=1 // Fanout_BGA (Default Rule)
FanoutControl Fanout_Default [All] p4: bgadir=Out bgaviamode=Centered fanoutstyle=Auto fanoutdirection=Alternating viagrid=1 // Fanout_Default (Default Rule)
FanoutControl Fanout_Small [(CompPinCount < 5)] p5: bgadir=Out bgaviamode=Centered fanoutstyle=Auto fanoutdirection=OutThenIn viagrid=1 // Fanout_Small (Default Rule)
HoleSize [All] p1: absolutevalues=TRUE maxlimit=260 minlimit=7.87 maxpercent=80.000 minpercent=20.000
MinimumAnnularRing MinimumAnnularRing_ThermalPadVias [IsVia and InAnyComponent] p1: minimumring=5.91
MinimumAnnularRing [All] p2: minimumring=6
MinimumSolderMaskSliver MinimumSolderMaskSliver_Logo [InComponentClass('Logo') vs InComponentClass('Logo')] p1: minsoldermaskwidth=0.7
MinimumSolderMaskSliver [All] p2: minsoldermaskwidth=3.94
PlaneConnect [All] p1: planeconnectstyle=Direct reliefexpansion=10 reliefentries=4 reliefconductorwidth=10 reliefairgap=10
PolygonConnect [All] p1: connectstyle=Direct reliefconductorwidth=10 reliefentries=4 polygonreliefangle="90 Angle" airgapwidth=10
RoomDefinition P1 [InComponentClass('P1')] p1: confinementstyle=ConfineIn formatcopy=TRUE lockcomponents=FALSE outline 1105.59,1932.2 2405.59,1932.2 2405.59,3932.2 1105.59,3932.2
RoomDefinition P2 [InComponentClass('P2')] p2: confinementstyle=ConfineIn formatcopy=FALSE lockcomponents=FALSE outline 1105.59,62.2 2405.59,62.2 2405.59,2062.2 1105.59,2062.2
RoutingVias ThermalPadVias [IsVia and InAnyComponent] p1: holewidth=7.87 width=19.68 viastyle="Through Hole" minholewidth=7.87 minwidth=16 maxholewidth=32 maxwidth=32
RoutingVias [All] p2: holewidth=10 width=26 viastyle="Through Hole" minholewidth=7.87 minwidth=22 maxholewidth=40 maxwidth=65 viatemplateguid#1={873F0AA8-BE06-43F5-8FAA-81F22515707D} viatemplatename#1=v56h25m0mx0
SilkToBoardRegionClearance [Not ((IsComment or IsDesignator) And (Hide <> 'False')) and not InRegion(1000,500,4000,800)] p1:
SilkToSilkClearance SilkToSilkClearance_Pb-FreeLogo [(HasFootprint('Pb-Free_Overlay_Medium') OR HasFootprint('Pb-Free_Overlay_Small')) vs (HasFootprint('Pb-Free_Overlay_Medium') OR HasFootprint('Pb-Free_Overlay_Small'))] p1: silktosilkclearance=0
SilkToSilkClearance [All] p2: silktosilkclearance=3
SilkToSolderMaskClearance SilkToComponentPadClearance [IsPad and InAnycomponent] p1: minsilkscreentomaskgap=3 clearancetoexposedcopper=TRUE
SilkToSolderMaskClearance "Silk to Solder Mask Opening" [All] p2: minsilkscreentomaskgap=3 clearancetoexposedcopper=FALSE
SolderMaskExpansion [All] p1: expansion=1.97
Width [All] p1: maxlimit=100 minlimit=8 preferedwidth=10 checkconnectedcopper=TRUE
15 further rules are at their usual default settings.

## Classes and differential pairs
channel class PWR856A_room: P1 P2
component class P1: C1_P1 C2_P1 C3_P1 C4_P1 C5_P1 C6_P1 C7_P1 C8_P1 C9_P1 C10_P1 C11_P1 C12_P1 C13_P1 C14_P1 C15_P1 C16_P1 C17_P1 C18_P1 C19_P1 C20_P1 C21_P1 C22_P1 D1_P1 J4_P1 JP1_P1 JP2_P1 NT1_P1 R1_P1 R2_P1 R3_P1 R4_P1 R5_P1 R6_P1 R7_P1 R8_P1 R9_P1 R10_P1 R11_P1 R12_P1 R13_P1 R14_P1 R15_P1 R16_P1 R17_P1 R18_P1 R19_P1 R20_P1 R21_P1 R22_P1 R23_P1 R24_P1 R25_P1 R26_P1 R27_P1 SMB1_P1 TP1_P1 TP2_P1 TP3_P1 TP4_P1 TP5_P1 U1_P1
component class P2: C1_P2 C2_P2 C3_P2 C4_P2 C5_P2 C6_P2 C7_P2 C8_P2 C9_P2 C10_P2 C11_P2 C12_P2 C13_P2 C14_P2 C15_P2 C16_P2 C17_P2 C18_P2 C19_P2 C20_P2 C21_P2 C22_P2 D1_P2 J4_P2 JP1_P2 JP2_P2 NT1_P2 R1_P2 R2_P2 R3_P2 R4_P2 R5_P2 R6_P2 R7_P2 R8_P2 R9_P2 R10_P2 R11_P2 R12_P2 R13_P2 R14_P2 R15_P2 R16_P2 R17_P2 R18_P2 R19_P2 R20_P2 R21_P2 R22_P2 R23_P2 R24_P2 R25_P2 R26_P2 R27_P2 SMB1_P2 TP1_P2 TP2_P2 TP3_P2 TP4_P2 TP5_P2 U1_P2
component class AssemblyNote: ZZ1 ZZ2 ZZ3 ZZ4 ZZ5
component class FiducialMark: FID1 FID2 FID3 FID4 FID5 FID6
component class Header: JP1_P1 JP1_P2 JP2_P1 JP2_P2 JP3 JP4
component class Label: LBL1
component class Shunt: SH-JP1 SH-JP2 SH-JP3 SH-JP4 SH-JP9 SH-JP10 SH-JP11 SH-JP12

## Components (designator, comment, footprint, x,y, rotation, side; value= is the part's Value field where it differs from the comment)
C1_P1 "Capacitor" 0603L 1820,2725 r270 bottom value=1uF (schematic designator C1)
C1_P2 "Capacitor" 0603L 1820,855 r270 bottom value=1uF (schematic designator C1)
C2_P1 "Cap_Polarized" SM_RADIAL_G 2040,3630 r0 top value=100uF (schematic designator C2)
C2_P2 "Cap_Polarized" SM_RADIAL_G 2040,1760 r0 top value=100uF (schematic designator C2)
C3_P1 "Capacitor" 1210_270 2010,3285 r0 top value=22uF (schematic designator C3)
C3_P2 "Capacitor" 1210_270 2010,1415 r0 top value=22uF (schematic designator C3)
C4_P1 "Capacitor" 1210_270 2010,3145 r0 top value=22uF (schematic designator C4)
C4_P2 "Capacitor" 1210_270 2010,1275 r0 top value=22uF (schematic designator C4)
C5_P1 "Capacitor" 1210_270 2010,3160 r180 bottom value=22uF (schematic designator C5)
C5_P2 "Capacitor" 1210_270 2010,1290 r180 bottom value=22uF (schematic designator C5)
C6_P1 "Capacitor" 1210_270 2040,3030 r180 bottom value=22uF (schematic designator C6)
C6_P2 "Capacitor" 1210_270 2040,1160 r180 bottom value=22uF (schematic designator C6)
C7_P1 "Capacitor" 0402 2015,3045 r180 top value=6800pF (schematic designator C7)
C7_P2 "Capacitor" 0402 2015,1175 r180 top value=6800pF (schematic designator C7)
C8_P1 "Capacitor" 0402 2015,2995 r180 top value=6800pF (schematic designator C8)
C8_P2 "Capacitor" 0402 2015,1125 r180 top value=6800pF (schematic designator C8)
C9_P1 "Capacitor" 0402 1960,2905 r90 bottom value=6800pF (schematic designator C9)
C9_P2 "Capacitor" 0402 1960,1035 r90 bottom value=6800pF (schematic designator C9)
C10_P1 "Capacitor" 0603L 1860,2945 r90 bottom value=1uF (schematic designator C10)
C10_P2 "Capacitor" 0603L 1860,1075 r90 bottom value=1uF (schematic designator C10)
C11_P1 "Capacitor" 0603L 1850,3085 r270 top value=1uF (schematic designator C11)
C11_P2 "Capacitor" 0603L 1850,1215 r270 top value=1uF (schematic designator C11)
C12_P1 "Capacitor" 0603L 1955,2620 r270 bottom value=1000pF (schematic designator C12)
C12_P2 "Capacitor" 0603L 1955,750 r270 bottom value=1000pF (schematic designator C12)
C13_P1 "Capacitor" 0603L 1865,2520 r0 top value=0.1uF (schematic designator C13)
C13_P2 "Capacitor" 0603L 1865,650 r0 top value=0.1uF (schematic designator C13)
C14_P1 "Capacitor" 0603L 1745,2945 r90 bottom value=1uF (schematic designator C14)
C14_P2 "Capacitor" 0603L 1745,1075 r90 bottom value=1uF (schematic designator C14)
C15_P1 "Capacitor" 0603L 1782,3085 r270 top value=4.7uF (schematic designator C15)
C15_P2 "Capacitor" 0603L 1782,1215 r270 top value=4.7uF (schematic designator C15)
C16_P1 "C0603C104K5RACTU" 0603L 1800,2945 r90 bottom value=0.1uF (schematic designator C16)
C16_P2 "C0603C104K5RACTU" 0603L 1800,1075 r90 bottom value=0.1uF (schematic designator C16)
C17_P1 "Capacitor" 0603L 1625,2945 r270 top value=100pF (schematic designator C17)
C17_P2 "Capacitor" 0603L 1625,1075 r270 top value=100pF (schematic designator C17)
C18_P1 "Capacitor" 0603L 1715,2540 r270 top value=2.2uF (schematic designator C18)
C18_P2 "Capacitor" 0603L 1715,670 r270 top value=2.2uF (schematic designator C18)
C19_P1 "GRM188Z71C225KE43" 0603L 1745,2625 r0 top value=2.2uF (schematic designator C19)
C19_P2 "GRM188Z71C225KE43" 0603L 1745,755 r0 top value=2.2uF (schematic designator C19)
C20_P1 "C0603C104K5RACTU" 0603L 1525,3220 r90 bottom value=0.1uF (schematic designator C20)
C20_P2 "C0603C104K5RACTU" 0603L 1525,1350 r90 bottom value=0.1uF (schematic designator C20)
C21_P1 "Capacitor" 0603L 1625,2835 r270 top value=33pF (schematic designator C21)
C21_P2 "Capacitor" 0603L 1625,965 r270 top value=33pF (schematic designator C21)
C22 "Capacitor" 0805_HV 480,3885 r0 top value=1uF
C23 "Capacitor" 0805_HV 670,3885 r180 top value=10uF
C24 "Capacitor" 0603L 475,3560 r90 top value=0.01uF
C25 "Capacitor" 1210_270 3740,1975 r90 top value=47uF
C26 "Capacitor" 1210_270 3425,920 r0 bottom value=47uF
C27 "Capacitor" 1210_270 3425,770 r0 bottom value=47uF
C28 "Capacitor" 1210_270 3425,620 r0 bottom value=47uF
C29 "Capacitor" 1210_270 2500,2015 r180 bottom value=47uF
C30 "Capacitor" 1210_270 2500,2145 r180 bottom value=47uF
C31 "Capacitor" 1210_270 2500,2030 r180 top value=47uF
C32 "Capacitor" 1210_270 2500,2160 r180 top value=47uF
C33 "Cap_Polarized" SM_RADIAL_G 250,1975 r270 top value=100uF
C34 "Cap_Polarized" SM_RADIAL_G 700,1975 r270 top value=100uF
C35 "Capacitor" 1210_270 2500,2870 r0 top value=47uF
C36 "Capacitor" 1210_270 2500,3000 r0 top value=47uF
C37 "Capacitor" 1210_270 2500,3370 r0 top value=47uF
C38 "Capacitor" 1210_270 2500,3500 r0 top value=47uF
C39 "Capacitor" 1210_270 2500,3630 r0 top value=47uF
C40 "Capacitor" 1210_270 2500,3760 r0 top value=47uF
C41 "Capacitor" 1210_270 2500,2850 r0 bottom value=47uF
C42 "Capacitor" 1210_270 2500,2980 r0 bottom value=47uF
C43 "Capacitor" 1210_270 2500,3340 r0 bottom value=47uF
C44 "Capacitor" 1210_270 2500,3470 r0 bottom value=47uF
C45 "Capacitor" 1210_270 2500,3600 r0 bottom value=47uF
C46 "Capacitor" 1210_270 2500,3730 r0 bottom value=47uF
C47 "Cap_Polarized" 7343-40 2500,3185 r180 top value=470uF
C48 "Cap_Polarized" 7343-40 2500,3160 r180 bottom value=470uF
C49 "Capacitor" 1210_270 3720,1975 r270 bottom value=47uF
C50 "Capacitor" 1210_270 3585,1975 r270 bottom value=47uF
C51 "Capacitor" 1210_270 2500,1005 r0 top value=47uF
C52 "Capacitor" 1210_270 2500,1135 r0 top value=47uF
C53 "Capacitor" 1210_270 2500,1510 r0 top value=47uF
C54 "Capacitor" 1210_270 2500,1640 r0 top value=47uF
C55 "Capacitor" 1210_270 2500,1770 r0 top value=47uF
C56 "Capacitor" 1210_270 2500,1900 r0 top value=47uF
C57 "Capacitor" 1210_270 2500,1005 r0 bottom value=47uF
C58 "Capacitor" 1210_270 2500,1135 r0 bottom value=47uF
C59 "Capacitor" 1210_270 2500,1495 r0 bottom value=47uF
C60 "Capacitor" 1210_270 2500,1625 r0 bottom value=47uF
C61 "Capacitor" 1210_270 2500,1755 r0 bottom value=47uF
C62 "Capacitor" 1210_270 2500,1885 r0 bottom value=47uF
C63 "Cap_Polarized" 7343-40 2500,1325 r180 top value=470uF
C64 "Cap_Polarized" 7343-40 2500,1315 r180 bottom value=470uF
C65 "Capacitor" 1210_270 3425,3330 r0 bottom value=47uF
C66 "Capacitor" 1210_270 3425,3180 r0 bottom value=47uF
C67 "Capacitor" 1210_270 3425,3030 r0 bottom value=47uF
C68 "Capacitor" 1210_270 3605,1975 r90 top value=47uF
C69 "Capacitor" 1210_270 2500,180 r180 bottom value=47uF
C70 "Capacitor" 1210_270 2500,310 r180 bottom value=47uF
C71 "Capacitor" 1210_270 2500,165 r180 top value=47uF
C72 "Capacitor" 1210_270 2500,295 r180 top value=47uF
D1_P1 "DIODE_SCHOTTKY" SOD-523 1815,2515 r90 bottom value=30V (schematic designator D1)
D1_P2 "DIODE_SCHOTTKY" SOD-523 1815,645 r90 bottom value=30V (schematic designator D1)
FID1 "Fiducial" Fiducial10-20 100,100 r90 top
FID2 "Fiducial" Fiducial10-20 3900,3900 r90 top
FID3 "Fiducial" Fiducial10-20 3900,100 r90 top
FID4 "Fiducial" Fiducial10-20 100,100 r180 bottom
FID5 "Fiducial" Fiducial10-20 3900,3900 r180 bottom
FID6 "Fiducial" Fiducial10-20 3900,100 r180 bottom
H3 "Bumpon" Bumpon_SJ5003Transparent 500,3750 r180 bottom
H4 "Bumpon" Bumpon_SJ5003Transparent 3680,3750 r180 bottom
H5 "Bumpon" Bumpon_SJ5003Transparent 500,250 r180 bottom
H6 "Bumpon" Bumpon_SJ5003Transparent 3680,250 r180 bottom
J1 "Receptacle_6x2" Samtec_SSW-106-23-x-D 2915,1200 r90 top
J2 "Header_5x2" CONN_5103308-1 225,625 r270 top
J3 "Receptacle_6x2" Samtec_SSW-106-23-x-D 2915,2000 r90 top
JP1_P1 "Header_2x1" Sullins_Gxx02SAAN 1625,3365 r0 top (schematic designator JP1)
JP1_P2 "Header_2x1" Sullins_Gxx02SAAN 1625,1495 r0 top (schematic designator JP1)
JP2_P1 "Header_3x2" Sullins_PBC03DAAN 1315,3185 r180 top (schematic designator JP2)
JP2_P2 "Header_3x2" Sullins_PBC03DAAN 1315,1315 r180 top (schematic designator JP2)
JP3 "Header_2x1" TE_5-146278-2 780,3700 r270 top
JP4 "Header_2x1" TE_5-146278-2 575,3400 r180 top
L1 "Inductor_Iron" SLC1480 2350,2515 r0 top value=300nH
L2 "Inductor_Iron" SLC1480 2350,650 r0 top value=300nH
LBL1 ".EVM_orderable" Label_650x200 3150,3400 r0 top
LED1 "LED_A2_K1" WL-SMCW_GREEN 625,150 r180 top value=Green
Logo1 "CAUTION HOT SURFACE" IEC_HotSurface_Small 1076.5,1974.5 r0 top
Logo4 "WEEE logo" WEEE_Minimum 3410,890 r0 top
Logo5 "FCC disclaimer" FCC_disclaimer 1621,76 r0 top
NT1_P1 "Net-Tie" Net-Tie_10mil 1735,2825.1 r0 top net-tie (schematic designator NT1)
NT1_P2 "Net-Tie" Net-Tie_10mil 1735,955.1 r0 top net-tie (schematic designator NT1)
R1_P1 "Resistor" 0603L 1820,2620 r270 bottom value=0 (schematic designator R1)
R1_P2 "Resistor" 0603L 1820,750 r270 bottom value=0 (schematic designator R1)
R2_P1 "Resistor" 0603L 1800,3220 r90 bottom value=0 (schematic designator R2)
R2_P2 "Resistor" 0603L 1800,1350 r90 bottom value=0 (schematic designator R2)
R3_P1 "CRCW060310R0JNEA" 0603L 1885,3055 r0 bottom value=10 (schematic designator R3)
R3_P2 "CRCW060310R0JNEA" 0603L 1885,1185 r0 bottom value=10 (schematic designator R3)
R4_P1 "Resistor" 0603L 1840,2605 r90 top value=0 (schematic designator R4)
R4_P2 "Resistor" 0603L 1840,735 r90 top value=0 (schematic designator R4)
R5_P1 "Resistor" 0603L 1900,2620 r90 bottom value=49.9 (schematic designator R5)
R5_P2 "Resistor" 0603L 1900,750 r90 bottom value=49.9 (schematic designator R5)
R6_P1 "Resistor" 1206 2035,2660 r270 bottom value=1.0 (schematic designator R6)
R6_P2 "Resistor" 1206 2035,790 r270 bottom value=1.0 (schematic designator R6)
R7_P1 "RC0603FR-075K11L" 0603L 1655,2620 r270 bottom value=5.11k (schematic designator R7)
R7_P2 "RC0603FR-075K11L" 0603L 1655,750 r270 bottom value=5.11k (schematic designator R7)
R8_P1 "Resistor" 0603L 1540,2885 r0 top value=10.0k (schematic designator R8)
R8_P2 "Resistor" 0603L 1540,1015 r0 top value=10.0k (schematic designator R8)
R9_P1 "RC0603FR-0730K1L" 0603L 1580,3220 r90 bottom value=30.1k (schematic designator R9)
R9_P2 "RC0603FR-0730K1L" 0603L 1580,1350 r90 bottom value=30.1k (schematic designator R9)
R10_P1 "Resistor" 0603L 1690,3110 r90 top value=10.5k (schematic designator R10)
R10_P2 "Resistor" 0603L 1690,1240 r90 top value=10.5k (schematic designator R10)
R11_P1 "Resistor" 0603L 1630,3110 r90 top value=10.5k (schematic designator R11)
R11_P2 "Resistor" 0603L 1630,1240 r90 top value=10.5k (schematic designator R11)
R12_P1 "Resistor" 0603L 1570,3110 r90 top value=10.5k (schematic designator R12)
R12_P2 "Resistor" 0603L 1570,1240 r90 top value=10.5k (schematic designator R12)
R13_P1 "Resistor" 0603L 1510,3110 r90 top value=53.6k (schematic designator R13)
R13_P2 "Resistor" 0603L 1510,1240 r90 top value=53.6k (schematic designator R13)
R14_P1 "ERJ-3EKF7501V" 0603L 1470,3220 r90 bottom value=7.50k (schematic designator R14)
R14_P2 "ERJ-3EKF7501V" 0603L 1470,1350 r90 bottom value=7.50k (schematic designator R14)
R15_P1 "Resistor" 0603L 1540,2830 r0 top value=0 (schematic designator R15)
R15_P2 "Resistor" 0603L 1540,960 r0 top value=0 (schematic designator R15)
R16_P1 "Resistor" 0603L 1540,2705 r180 top value=0 (schematic designator R16)
R16_P2 "Resistor" 0603L 1540,835 r180 top value=0 (schematic designator R16)
R17_P1 "Resistor" 0603L 1540,2760 r0 top value=0 (schematic designator R17)
R17_P2 "Resistor" 0603L 1540,890 r0 top value=0 (schematic designator R17)
R18_P1 "Resistor" 0603L 1690,3220 r90 top value=10.5k (schematic designator R18)
R18_P2 "Resistor" 0603L 1690,1350 r90 top value=10.5k (schematic designator R18)
R19_P1 "Resistor" 0603L 1630,3220 r90 top value=0 (schematic designator R19)
R19_P2 "Resistor" 0603L 1630,1350 r90 top value=0 (schematic designator R19)
R20_P1 "Resistor" 0603L 1570,3220 r90 top value=10.5k (schematic designator R20)
R20_P2 "Resistor" 0603L 1570,1350 r90 top value=10.5k (schematic designator R20)
R21_P1 "Resistor" 0603L 1510,3220 r90 top value=24.9k (schematic designator R21)
R21_P2 "Resistor" 0603L 1510,1350 r90 top value=24.9k (schematic designator R21)
R22_P1 "Resistor" 0603L 1540,2650 r180 top value=0 (schematic designator R22)
R22_P2 "Resistor" 0603L 1540,780 r180 top value=0 (schematic designator R22)
R23_P1 "Resistor" 0603L 1540,2540 r180 top value=0 (schematic designator R23)
R23_P2 "Resistor" 0603L 1540,670 r180 top value=0 (schematic designator R23)
R24_P1 "Resistor" 0603L 1540,2595 r0 top value=0 (schematic designator R24)
R24_P2 "Resistor" 0603L 1540,725 r0 top value=0 (schematic designator R24)
R25_P1 "Resistor" 0603L 1540,2485 r180 top value=0 (schematic designator R25)
R25_P2 "Resistor" 0603L 1540,615 r180 top value=0 (schematic designator R25)
R26_P1 "Resistor" 0603L 1655,2725 r90 bottom value=10.0k (schematic designator R26)
R26_P2 "Resistor" 0603L 1655,855 r90 bottom value=10.0k (schematic designator R26)
R27_P1 "Resistor" 0603L 1770,2540 r270 top value=0 (schematic designator R27)
R27_P2 "Resistor" 0603L 1770,670 r270 top value=0 (schematic designator R27)
R28 "Resistor" 0603L 500,150 r0 top value=1.00k
R29 "Resistor" 0603L 660,3560 r90 top value=47.5k
R30 "Resistor" 0603L 530,3560 r270 top value=15.0k
R31 "Resistor" 0603L 585,3560 r270 top value=560k
R32 "Resistor" 0603L 1540,2995 r180 top value=0
R33 "Resistor" 0603L 1540,2940 r180 top value=0
R34 "Resistor" 0603L 3830,3090 r0 bottom value=49.9
R35 "Resistor" 0603L 3845,1945 r0 bottom value=49.9
R36 "Resistor" 0603L 3845,2005 r0 bottom value=49.9
R37 "Resistor" 0603L 1540,1130 r180 top value=0
R38 "Resistor" 0603L 3830,3320 r180 bottom value=49.9
R39 "Resistor" 0603L 1540,1075 r180 top value=0
SH-JP1 "969102-0000-DA" SNT-100-BK-G 1315,3085 r0 top value=1x2
SH-JP2 "969102-0000-DA" SNT-100-BK-G 575,3405 r0 top value=1x2
SH-JP3 "969102-0000-DA" SNT-100-BK-G 780,3695 r90 top value=1x2
SH-JP4 "969102-0000-DA" SNT-100-BK-G 1310,1220 r0 top value=1x2
SMB1_P1 "SMA_Contact1_GND2" JAE_SMBR004D00 1625,2185 r0 top (schematic designator SMB1)
SMB1_P2 "SMA_Contact1_GND2" JAE_SMBR004D00 1625,315 r0 top (schematic designator SMB1)
SMB2 "SMA_Contact1_GND2" JAE_SMBR004D00 3335,1975 r0 top
T1 "1935776" Phoenix_1935776 205,2600 r270 top
T2 "1935776" Phoenix_1935776 205,1400 r270 top
T3 "CB70-14-CY" CB70-14-CY 3410,1425 r180 top
T4 "Receptacle_2x1" TERM_BLK_ED555-2DS 210,3870 r270 top
T5 "CB70-14-CY" CB70-14-CY 3410,2525 r180 top
TP1_P1 "5010" Keystone5010 1525,3875 r0 top (schematic designator TP1)
TP1_P2 "5010" Keystone5010 1400,1650 r0 top (schematic designator TP1)
TP2_P1 "5012" Keystone5012 1870,2185 r0 top (schematic designator TP2)
TP2_P2 "5012" Keystone5012 1870,315 r0 top (schematic designator TP2)
TP3_P1 "5011" Keystone5011 1700,3875 r0 top (schematic designator TP3)
TP3_P2 "5011" Keystone5011 1225,1650 r0 top (schematic designator TP3)
TP4_P1 "5011" Keystone5011 1395,2185 r0 top (schematic designator TP4)
TP4_P2 "5011" Keystone5011 1395,315 r0 top (schematic designator TP4)
TP5_P1 "5012" Keystone5012 1250,2425 r0 top (schematic designator TP5)
TP5_P2 "5012" Keystone5012 1250,550 r0 top (schematic designator TP5)
TP6 "5010" Keystone5010 950,3875 r0 top
TP7 "5012" Keystone5012 625,705 r0 top
TP8 "5012" Keystone5012 625,905 r0 top
TP9 "5012" Keystone5012 625,1105 r0 top
TP10 "5012" Keystone5012 625,505 r0 top
TP11 "5011" Keystone5011 125,3500 r90 top
TP12 "5010" Keystone5010 625,2550 r90 top
TP13 "5010" Keystone5010 3025,3875 r0 top
TP14 "5010" Keystone5012 3800,3200 r90 top
TP15 "5011" Keystone5011 625,1425 r90 top
TP16 "5011" Keystone5011 2850,3875 r0 top
TP17 "5012" Keystone5012 3425,425 r0 top
TP18 "5012" Keystone5012 3225,425 r0 top
TP19 "5010" Keystone5010 325,3500 r90 top
TP20 "5011" Keystone5011 3325,225 r0 top
TP21 "5012" Keystone5012 125,3275 r90 top
TP22 "5012" Keystone5010 3800,800 r90 top
TP23 "5011" Keystone5011 900,225 r0 top
TP24 "5011" Keystone5011 125,3050 r90 top
TP25 "5011" Keystone5011 3800,575 r90 top
TP26 "5010" Keystone5010 3075,225 r0 top
TP27 "5012" Keystone5012 1125,225 r0 top
TP28 "5011" Keystone5012 3800,3425 r90 top
TP29 "5012" Keystone5012 1250,2625 r0 top
TP30 "5011" Keystone5011 2900,225 r0 top
TP31 "5012" Keystone5012 1250,2825 r0 top
TP32 "5011" Keystone5011 1175,3875 r0 top
U1_P1 "TPS546D24RVFR" RVF0040A_NV 1845,2835 r90 top (schematic designator U1)
U1_P2 "TPS546D24RVFR" RVF0040A_NV 1845,965 r90 top (schematic designator U1)
U2 "LP38798SD-ADJ" DNT0012B 540,3720 r0 top
ZZ1 "This Assembly Note is for PCB labels only" AssemblyNoteLabel 225,4675 r0 top
ZZ2 "These assemblies are ESD sensitive, ESD precautions shall be observed." AssemblyNote 225,4575 r0 top
ZZ3 "These assemblies must be clean and free from flux and all contaminants. Use of no clean flux is not acceptable." AssemblyNote 225,4475 r0 top
ZZ4 "These assemblies must comply with workmanship standards IPC-A-610 Class 2, unless otherwise specified." AssemblyNote 225,4375 r0 top
ZZ5 "All Panduit CB70-14-CY parts must be soldered in to the board on indicated sides and fastened with screw, washer and nut" AssemblyNote 225,4275 r0 top

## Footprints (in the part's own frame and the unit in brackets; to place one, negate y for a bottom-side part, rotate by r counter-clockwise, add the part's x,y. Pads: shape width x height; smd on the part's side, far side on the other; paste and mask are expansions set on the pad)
0402 [mm] "0402 from SM-752 data"
  rect 0.8x0.6 smd: 1(-0.6,0) 2(0.6,0)
  silkscreen extent -1.22,-0.52 1.22,0.52, body extent -0.55,-0.3 0.55,0.3, height 0.6
0603L [mm] "0603 from SM-752 data"
  rect 0.8x0.85 smd: 1(-0.7,0) 2(0.7,0)
  silkscreen extent -0.07,-0.33 0.07,0.33, body extent -0.87,-0.47 0.87,0.47, height 1
0805_HV [mil] "0805 with 30mil clearance between pads"
  rect 50x63 smd: 1(-40,0) 2(40,0)
  silkscreen extent -74,-40 74,40, body extent -43,-29 43,29, height 57
1206 [mm] "1206 from SM-752 data"
  rect 1.3x1.85 smd: 1(-1.45,0) 2(1.45,0)
  silkscreen extent -2.4,-1.21 2.4,1.21, body extent -1.7,-0.9 1.7,0.9, height 1.35
1210_270 [mm] "1210"
  rect 1.3x2.7 smd: 1(-1.45,0) 2(1.45,0)
  silkscreen extent -2.32,-1.57 2.32,1.57, body extent -1.7,-1.35 1.7,1.35, height 2.7
7343-40 [mm] "Molded, 2-Leads, Body 7.3x4.3mm, Height 4mm"
  rect 2.4x2.9 smd: 1(-3.05,0) 2(3.05,0)
  silkscreen extent -3.8,-2.25 3.8,2.25, body extent -3.8,-2.25 3.8,2.25, height 4.01
AssemblyNote [mil] "Assembly Note"
AssemblyNoteLabel [mil] "Assembly Note for PCB Labels"
Bumpon_SJ5003Transparent [mil] "3M Hemispherical Bumpon transparent"
  round 1 on Mech4: 0(0,0)
  silkscreen extent -228,-228 228,228, body extent -219,-219 219,219, height 197
CB70-14-CY [mil] "Terminal 90A Lug"
  rect 680x500 hole 254 copper offset -90,0 paste-250: 1(0,0)
  body extent -1300,-260 250,260, height 714
CONN_5103308-1 [mm] "TE Connectivity (AMP) Rev E datasheet"
  rect 1.65x1.65 hole 1.016 mask+0: 1(-5.08,-1.27)
  round 1.65 hole 1.016 mask+0: 2(-5.08,1.27) 3(-2.54,-1.27) 4(-2.54,1.27) 5(0,-1.27) 6(0,1.27) 7(2.54,-1.27) 8(2.54,1.27) 9(5.08,-1.27) 10(5.08,1.27)
  silkscreen extent -10.16,-5.33 10.16,4.57, body extent -10.16,-4.57 10.16,4.57, height 9.87
DNT0012B [mm] "SON, 12-Leads, Body 4x4mm, Pitch 0.5mm"
  rrect40% 0.6x0.25 smd: 1(-1.9,1.25) 2(-1.9,0.75) 3(-1.9,0.25) 4(-1.9,-0.25) 5(-1.9,-0.75) 6(-1.9,-1.25) 7(1.9,-1.25) 8(1.9,-0.75) 9(1.9,-0.25) 10(1.9,0.25) 11(1.9,0.75) 12(1.9,1.25)
  rrect4% 2.6x3 smd paste-1.3: 13(0,0)
  silkscreen extent -2.2,-2.2 2.2,2.2, body extent -2,-2 2,2, height 0.81
FCC_disclaimer [mil]
Fiducial10-20 [mm]
  round 1 smd mask+0.5: 1(0,0)
  Top Layer keep-out circle w1.178: c0,0 r0.5
IEC_HotSurface_Small [mil]
  silkscreen extent -107,-93 107,92
JAE_SMBR004D00 [mm] "Connector, Receptacle, TH"
  rect 1.7x0.8 smd: 1(2.15,0)
  round 1 smd: 2(-2,0)
  Top Layer region: -2.694,-1.817 -1.635,-2.809 -0.249,-3.24 1.186,-3.026 2.385,-2.208 3.108,-0.95 3.108,-0.95 0.455,-0.946 -0.059,-1.048 -0.559,-0.889 -0.919,-0.508 -1.05,0 -0.919,0.508 -0.559,0.889 -0.059,1.048 0.455,0.946 0.455,0.946 3.108,0.95 2.385,2.208 1.186,3.026 -0.249,3.24 -1.635,2.809 -2.694,1.817 -2.694,1.817
  body extent -2.2,-2.76 2.56,2.76, height 6.9
Keystone5010 [mil] "Keystone Multipurpose loops"
  round 87 hole 63: 1(0,0)
  silkscreen extent -70,-70 70,70, body extent -63,-63 63,62, height 319
Keystone5011 [mil] "Keystone Multipurpose loops"
  round 87 hole 63: 1(0,0)
  silkscreen extent -70,-70 70,70, body extent -63,-63 63,62, height 319
Keystone5012 [mil] "Keystone Multipurpose loops"
  round 87 hole 63: 1(0,0)
  silkscreen extent -70,-70 70,70, body extent -63,-63 63,62, height 319
Label_650x200 [mil] "Thermal Transfer Label"
  round 1 on Mech13: 0(0,0)
  silkscreen extent -325,-100 325,100, body extent -325,-100 325,100, height 1
Net-Tie_10mil [mil] "10mil net tie, no solder mask opening, no solder paste"
  rect 10x10 smd paste-5 mask-5: 1(-10,0) 2(10,0)
  Top Layer region: -6,5 6,5 6,-5 -6,-5
Phoenix_1935776 [mm] "Terminal Block, 2x1, 5mm, TH"
  rect 1.8x1.8 hole 1.3: 1(-2.5,0)
  round 1.8 hole 1.3: 2(2.5,0)
  silkscreen extent -5.3,-4.5 5,4.5, body extent -5,-4.5 5,4.5, height 13.5
RVF0040A_NV [mm]
  rrect40% 0.6x0.25 smd: 1(-2.4,2.75) 2(-2.4,2.25) 3(-2.4,1.75) 4(-2.4,1.25) 5(-2.4,0.75) 6(-2.4,0.25) 7(-2.4,-0.25) 8(-2.4,-0.75) 9(-2.4,-1.25) 10(-2.4,-1.75) 11(-2.4,-2.25) 12(-2.4,-2.75) 21(2.4,-2.75) 22(2.4,-2.25) 23(2.4,-1.75) 24(2.4,-1.25) 25(2.4,-0.75) 26(2.4,-0.25) 27(2.4,0.25) 28(2.4,0.75) 29(2.4,1.25) 30(2.4,1.75) 31(2.4,2.25) 32(2.4,2.75)
  rrect40% 0.25x0.6 smd: 13(-1.75,-3.4) 14(-1.25,-3.4) 15(-0.75,-3.4) 16(-0.25,-3.4) 17(0.25,-3.4) 18(0.75,-3.4) 19(1.25,-3.4) 20(1.75,-3.4) 33(1.75,3.4) 34(1.25,3.4) 35(0.75,3.4) 36(0.25,3.4) 37(-0.25,3.4) 38(-0.75,3.4) 39(-1.25,3.4) 40(-1.75,3.4)
  rrect9% 1.43x1.08 on Top Paste: 41(-0.815,1.92) 41(-0.815,-0.64) 41(-0.815,0.64) 41(-0.815,-1.92) 41(0.815,1.92) 41(0.815,-0.64) 41(0.815,0.64) 41(0.815,-1.92)
  rrect3% 3.3x5.3 smd paste-2: 41(0,0)
  silkscreen extent -2.7,-3.7 2.7,3.7, body extent -2.5,-3.5 2.5,3.5, height 1.52
Samtec_SSW-106-23-x-D [mm] "SAMTEC"
  rect 1.65x1.65 hole 1.15: 1(-6.35,1.27)
  round 1.65 hole 1.15: 2(-6.35,-1.27) 3(-3.81,1.27) 4(-3.81,-1.27) 5(-1.27,1.27) 6(-1.27,-1.27) 7(1.27,1.27) 8(1.27,-1.27) 9(3.81,1.27) 10(3.81,-1.27) 11(6.35,1.27) 12(6.35,-1.27)
  silkscreen extent -8.51,-2.54 8,2.46, body extent -7.87,-2.49 7.87,2.46, height 8.59
SLC1480 [mm] "Coilcraft"
  rect 4.95x6.35 smd: 1(-4.89,0) 2(4.89,0)
  silkscreen extent -6.73,-6.48 6.73,6.48, body extent -6.73,-6.48 6.73,6.48, height 8
SM_RADIAL_G [mm] "10 x 10.2mm:  Panasonic G"
  rect 4.1x2 smd: 1(-4.35,0) 2(4.35,0)
  silkscreen extent -5.35,-5.35 5.35,5.35, body extent -5.25,-5.25 5.25,5.25, height 10.5
SNT-100-BK-G [mil] "Samtec STEP model"
  round 1 on Mech3: 0(0,0)
  body extent -100,-50 100,50, height 344
SOD-523 [mm] "NXP Semiconductor recommended land pattern, nominal STEP model"
  rect 0.8x0.6 smd paste-0.05: 1(-0.55,0) 2(0.55,0)
  silkscreen extent -1.65,-0.66 1.2,0.66, body extent -0.8,-0.4 0.8,0.4, height 0.72
Sullins_Gxx02SAAN [mm] "Header, 2.54 mm, 2x1, TH"
  rect 1.55x1.55 hole 1.016: 1(-1.27,0)
  round 1.55 hole 1.016: 2(1.27,0)
  silkscreen extent -2.54,-1.75 2.54,1.27, body extent -2.54,-1.27 2.54,1.27, height 8.38
Sullins_PBC03DAAN [mm] "Sullins 100mil, 2x3, 230 mil above insulator"
  rect 1.65x1.65 hole 1.016: 1(-1.27,2.54)
  round 1.65 hole 1.016: 2(1.27,2.54) 3(-1.27,0) 4(1.27,0) 5(-1.27,-2.54) 6(1.27,-2.54)
  silkscreen extent -2.67,-3.81 2.54,4.58, body extent -2.54,-3.81 2.54,3.81, height 8.38
TE_5-146278-2 [mm] "TE CONNECTIVITY"
  rect 1.65x1.65 hole 1: 1(-1.27,0)
  round 1.65 hole 1: 2(1.27,0)
  silkscreen extent -2.92,-1.27 2.54,1.27, body extent -2.41,-1.17 2.41,1.17, height 8.13
TERM_BLK_ED555-2DS [mil]
  rrect4% 100x100 hole 50: 1(0,0)
  round 100 hole 50: 2(138,0)
  silkscreen extent -93,-161 215,113, body extent -69,-150 207,106, height 323
WEEE_Minimum [mil] "WEEElie bin"
  silkscreen extent -95,-172 99,104
WL-SMCW_GREEN [mm] "WURTH"
  rect 0.8x0.8 smd: 1(-0.8,0) 2(0.8,0)
  silkscreen extent -1.9,-0.8 1.2,0.8, body extent -0.85,-0.45 0.85,0.45, height 0.8

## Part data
C1_P1 C1_P2 C10_P1 C10_P2 C11_P1 C11_P2 C14_P1 C14_P2: library part CMP-0007405-4, "CAP, CERM, 1 uF, 25 V, +/- 10%, X7R, 0603", Cap_Case=0603, Manufacturer=MuRata, PartNumber=GRM188R71E105KA12D, Supplier Part Number 1=490-5307-1-ND, TempCo=X7R, Tolerance_%=10%, Value1=Unknown, Value2=25V, ValueDisplayed=1uF
C2_P1 C2_P2 C33 C34: library part CMP-0010663-1, "CAP, AL, 100 uF, 35 V, +/- 20%, 0.15 ohm, SMD", Cap_Case=G, Manufacturer=Panasonic, PartNumber=EEE-FC1V101P, Supplier Part Number 1=PCE4023CT-ND, Tolerance_%=20%, Value1="0.15 ohm", Value2=35V, ValueDisplayed=100uF
C3_P1 C3_P2 C4_P1 C4_P2 C5_P1 C5_P2 C6_P1 C6_P2: library part CMP-0009202-2, "CAP, CERM, 22 uF, 25 V, +/- 10%, X6S, 1210", Cap_Case=1210, Manufacturer=MuRata, PartNumber=GRM32EC81E226KE15L, Supplier Part Number 1=490-5310-1-ND, TempCo=X6S, Tolerance_%=10%, Value1=Unknown, Value2=25V, ValueDisplayed=22uF
C7_P1 C7_P2 C8_P1 C8_P2 C9_P1 C9_P2: library part CMP-0006696-2, "CAP, CERM, 6800 pF, 50 V, +/- 10%, X7R, 0402", Cap_Case=0402, Manufacturer=MuRata, PartNumber=GRM155R71H682KA88D, Supplier Part Number 1=490-4515-1-ND, TempCo=X7R, Tolerance_%=10%, Value1=Unknown, Value2=50V, ValueDisplayed=6800pF
C12_P1 C12_P2: library part CMP-0006723-4, "CAP, CERM, 1000 pF, 100 V, +/- 5%, X7R, 0603", Cap_Case=0603, Manufacturer=AVX, PartNumber=06031C102JAT2A, Supplier Part Number 1=478-3698-1-ND, TempCo=X7R, Tolerance_%=5%, Value1="0.276 ohm", Value2=100V, ValueDisplayed=1000pF
C13_P1 C13_P2: library part CMP-0006861-4, "CAP, CERM, 0.1 uF, 50 V, +/- 10%, X7R, 0603", Cap_Case=0603, Manufacturer=Kemet, PartNumber=C0603C104K5RACTU, Supplier Part Number 1=399-5089-1-ND, TempCo=X7R, Tolerance_%=10%, Value1=Unknown, Value2=50V, ValueDisplayed=0.1uF
C15_P1 C15_P2: library part CMP-0006949-5, "CAP, CERM, 4.7 uF, 10 V, +/- 10%, X5R, 0603", Cap_Case=0603, Manufacturer=Kemet, PartNumber=C0603C475K8PACTU, Supplier Part Number 1=399-5503-1-ND, TempCo=X5R, Tolerance_%=10%, Value1="0.006 ohm", Value2=10V, ValueDisplayed=4.7uF
C16_P1 C16_P2 C20_P1 C20_P2: library part CMP-0006861-4, "CAP, CERM, 0.1 uF, 50 V, +/- 10%, X7R, 0603", Cap_Case=0603, Manufacturer=Kemet, Supplier Part Number 1=399-5089-1-ND, TempCo=X7R, Tolerance_%=10%, Value1=Unknown, Value2=50V, ValueDisplayed=0.1uF
C17_P1 C17_P2: library part CMP-0007171-4, "CAP, CERM, 100 pF, 50 V, +/- 5%, C0G/NP0, 0603", Cap_Case=0603, Manufacturer=MuRata, PartNumber=GRM1885C1H101JA01D, Supplier Part Number 1=490-1427-1-ND, TempCo=C0G/NP0, Tolerance_%=5%, Value1=Unknown, Value2=50V, ValueDisplayed=100pF
C18_P1 C18_P2: library part CMP-0007499-4, "CAP, CERM, 2.2 uF, 16 V, +/- 10%, X7R, 0603", Cap_Case=0603, Manufacturer=MuRata, PartNumber=GRM188Z71C225KE43, Supplier Part Number 1=81-GRM188Z71C225KE3D, TempCo=X7R, Tolerance_%=10%, Value1=Unknown, Value2=16V, ValueDisplayed=2.2uF
C19_P1 C19_P2: library part CMP-0007499-4, "CAP, CERM, 2.2 uF, 16 V, +/- 10%, X7R, 0603", Cap_Case=0603, Manufacturer=MuRata, Supplier Part Number 1=81-GRM188Z71C225KE3D, TempCo=X7R, Tolerance_%=10%, Value1=Unknown, Value2=16V, ValueDisplayed=2.2uF
C21_P1 C21_P2: library part CMP-0006919-4, "CAP, CERM, 33 pF, 50 V, +/- 5%, C0G/NP0, 0603", Cap_Case=0603, Manufacturer=Kemet, PartNumber=C0603C330J5GACTU, Supplier Part Number 1=399-1055-1-ND, TempCo=C0G/NP0, Tolerance_%=5%, Value1=Unknown, Value2=50V, ValueDisplayed=33pF
C22: library part CMP-0008350-2, "CAP, CERM, 1 uF, 50 V, +/- 10%, X7R, 0805", Cap_Case=0805, Manufacturer=MuRata, PartNumber=GRM21BR71H105KA12L, Supplier Part Number 1=490-4736-1-ND, TempCo=X7R, Tolerance_%=10%, Value1=Unknown, Value2=50V, ValueDisplayed=1uF
C23: library part CMP-0008316-2, "CAP, CERM, 10 uF, 10 V, +/- 20%, X7R, 0805", Cap_Case=0805, Manufacturer=MuRata, PartNumber=GRM21BR71A106ME51L, Supplier Part Number 1=490-8316-1-ND, TempCo=X7R, Tolerance_%=20%, Value1=Unknown, Value2=10V, ValueDisplayed=10uF
C24: library part CMP-0007403-4, "CAP, CERM, 0.01 uF, 25 V, +/- 10%, X7R, 0603", Cap_Case=0603, Manufacturer=MuRata, PartNumber=GRM188R71E103KA01D, Supplier Part Number 1=490-1520-1-ND, TempCo=X7R, Tolerance_%=10%, Value1=Unknown, Value2=25V, ValueDisplayed=0.01uF
C25 C26 C27 C28 C29 C30 C31 C32 C35 C36 C37 C38 C39 C40 C41 C42 C43 C44 C45 C46 C49 C50 C51 C52 C53 C54 C55 C56 C57 C58 C59 C60 C61 C62 C65 C66 C67 C68 C69 C70 C71 C72: library part CMP-0009220-2, "CAP, CERM, 47 uF, 10 V, +/- 10%, X7R, 1210", Cap_Case=1210, Manufacturer=MuRata, PartNumber=GRM32ER71A476KE15L, Supplier Part Number 1=490-5312-1-ND, TempCo=X7R, Tolerance_%=10%, Value1=Unknown, Value2=10V, ValueDisplayed=47uF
